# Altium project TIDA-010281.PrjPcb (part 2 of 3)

## Sheet TIDA-010281_PMIC_BUCK.SchDoc
size 558 x 431 mm; Date: Not shown in title block; ApprovedBy: Not shown in title block; CheckedBy: Not shown in title block; Author: Not shown in title block; CompanyName: Not shown in title block; Engineer: Not shown in title block; Organization: Not shown in title block; Address1: Not shown in title block; Address2: Not shown in title block; Address3: Not shown in title block; Address4: Not shown in title block; DocumentNumber: 5; Revision: Use project parameter SCH_Rev; SheetNumber: 5; SheetTotal: 10; PageSetup: Record=PageOptions¦CenterHorizontal=True¦CenterVertical=True¦PrintScale=1.00¦XCorrection=1.00¦YCorrection=1.00¦PrintKind=0¦BorderSize=5000000¦LeftOffset=0¦BottomOffset=0¦Orientation=2¦PaperLength=1000¦PaperWidth=1000¦Scale=100¦PaperSource=15¦PrintQuality=600¦MediaType=1¦DitherType=10¦PaperKind=Letter¦PrintScaleMode=1
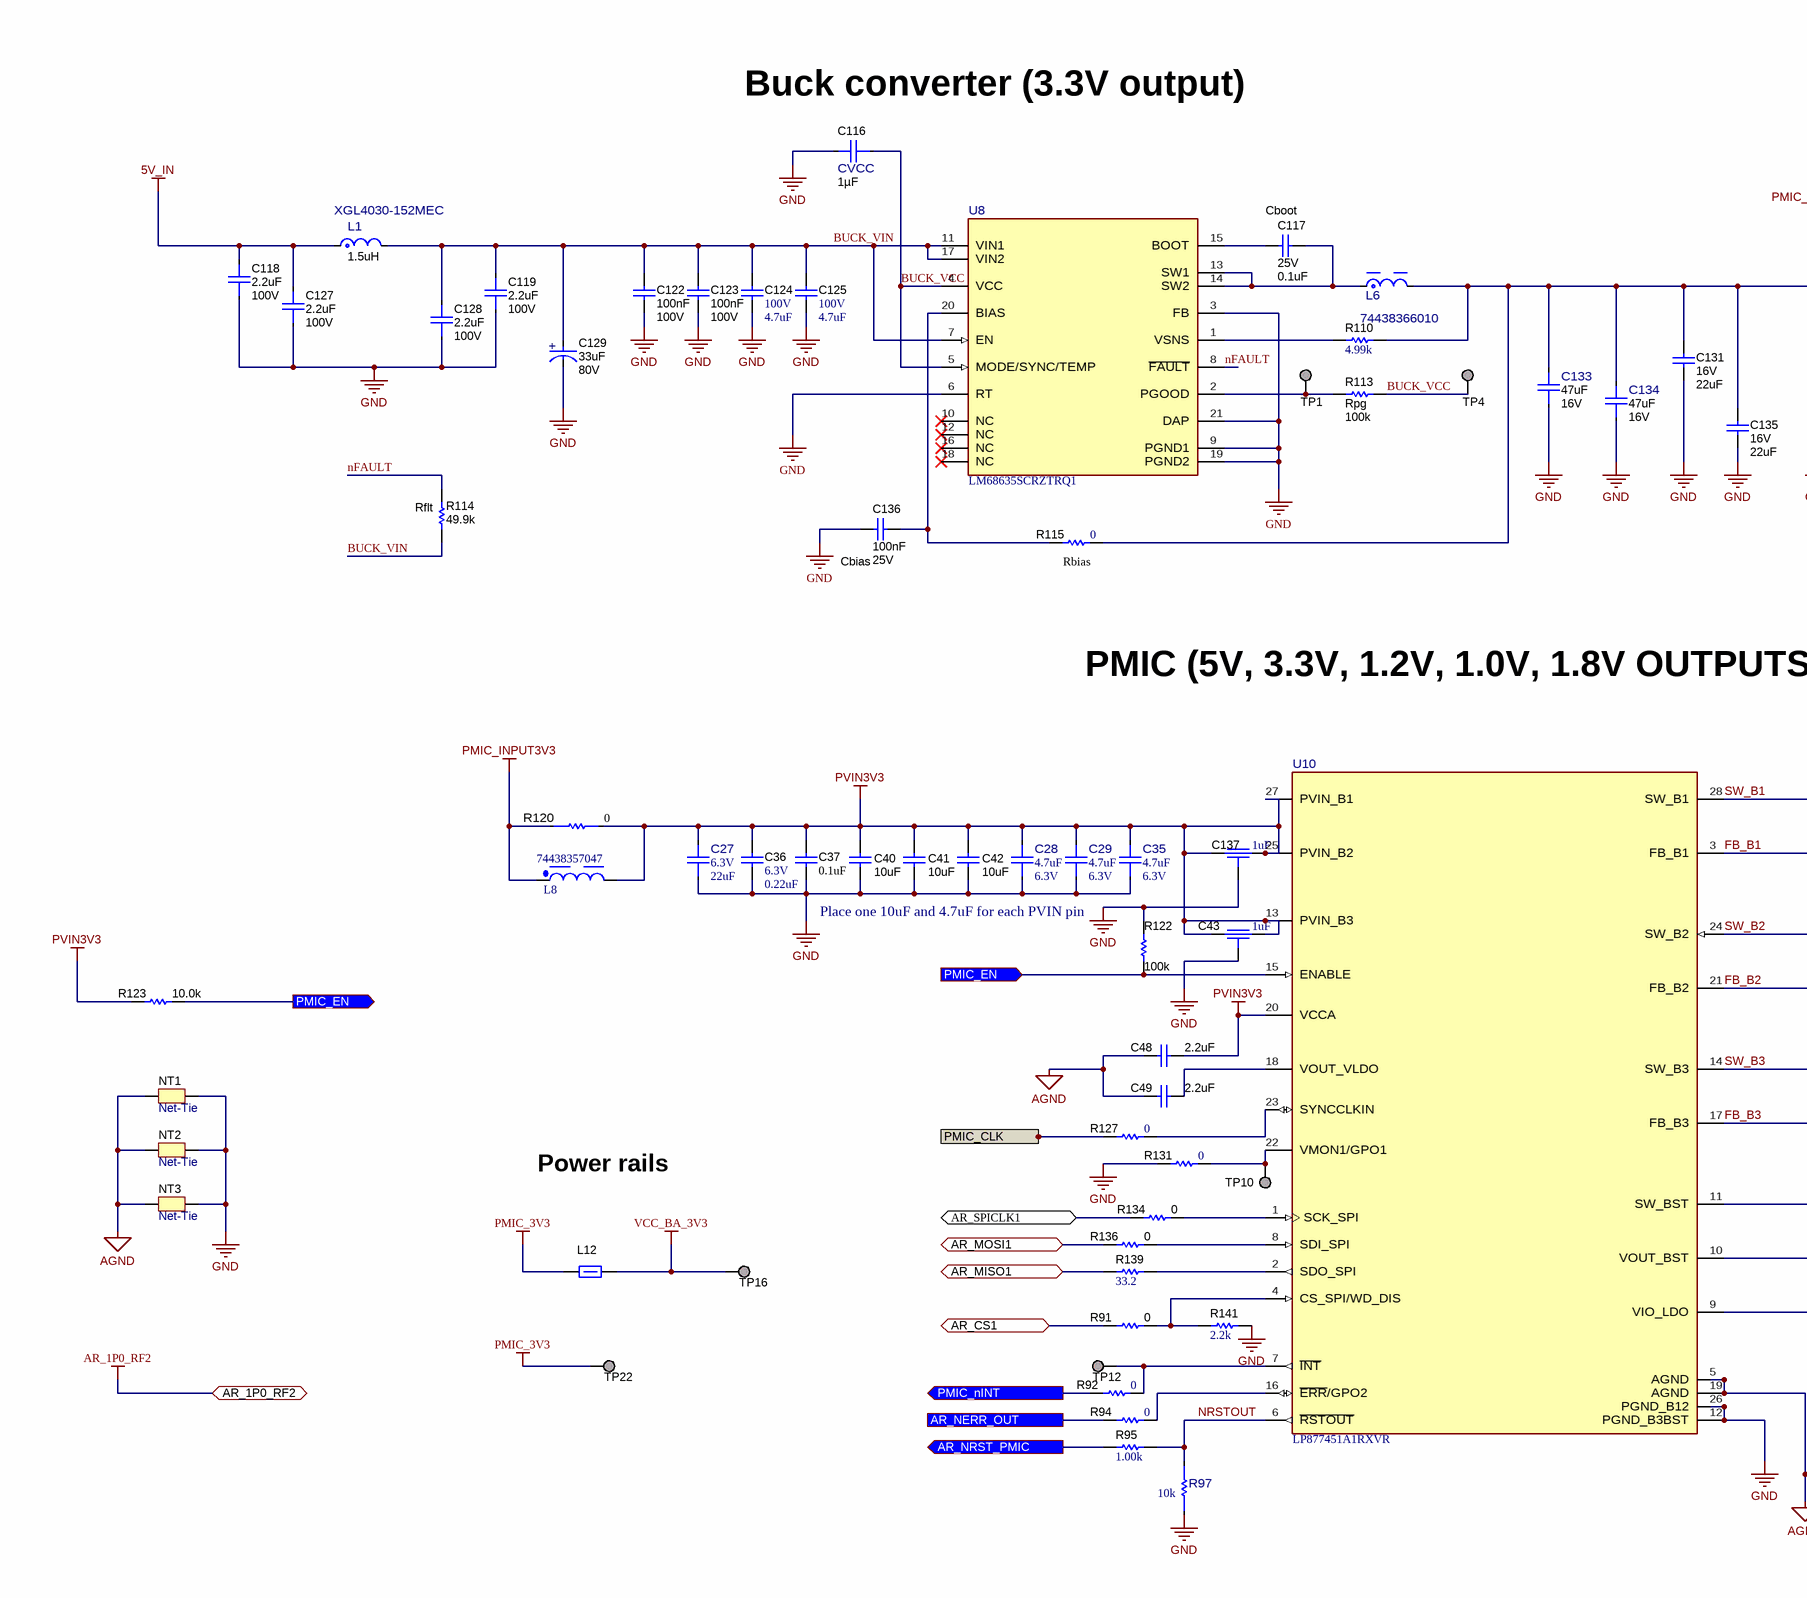
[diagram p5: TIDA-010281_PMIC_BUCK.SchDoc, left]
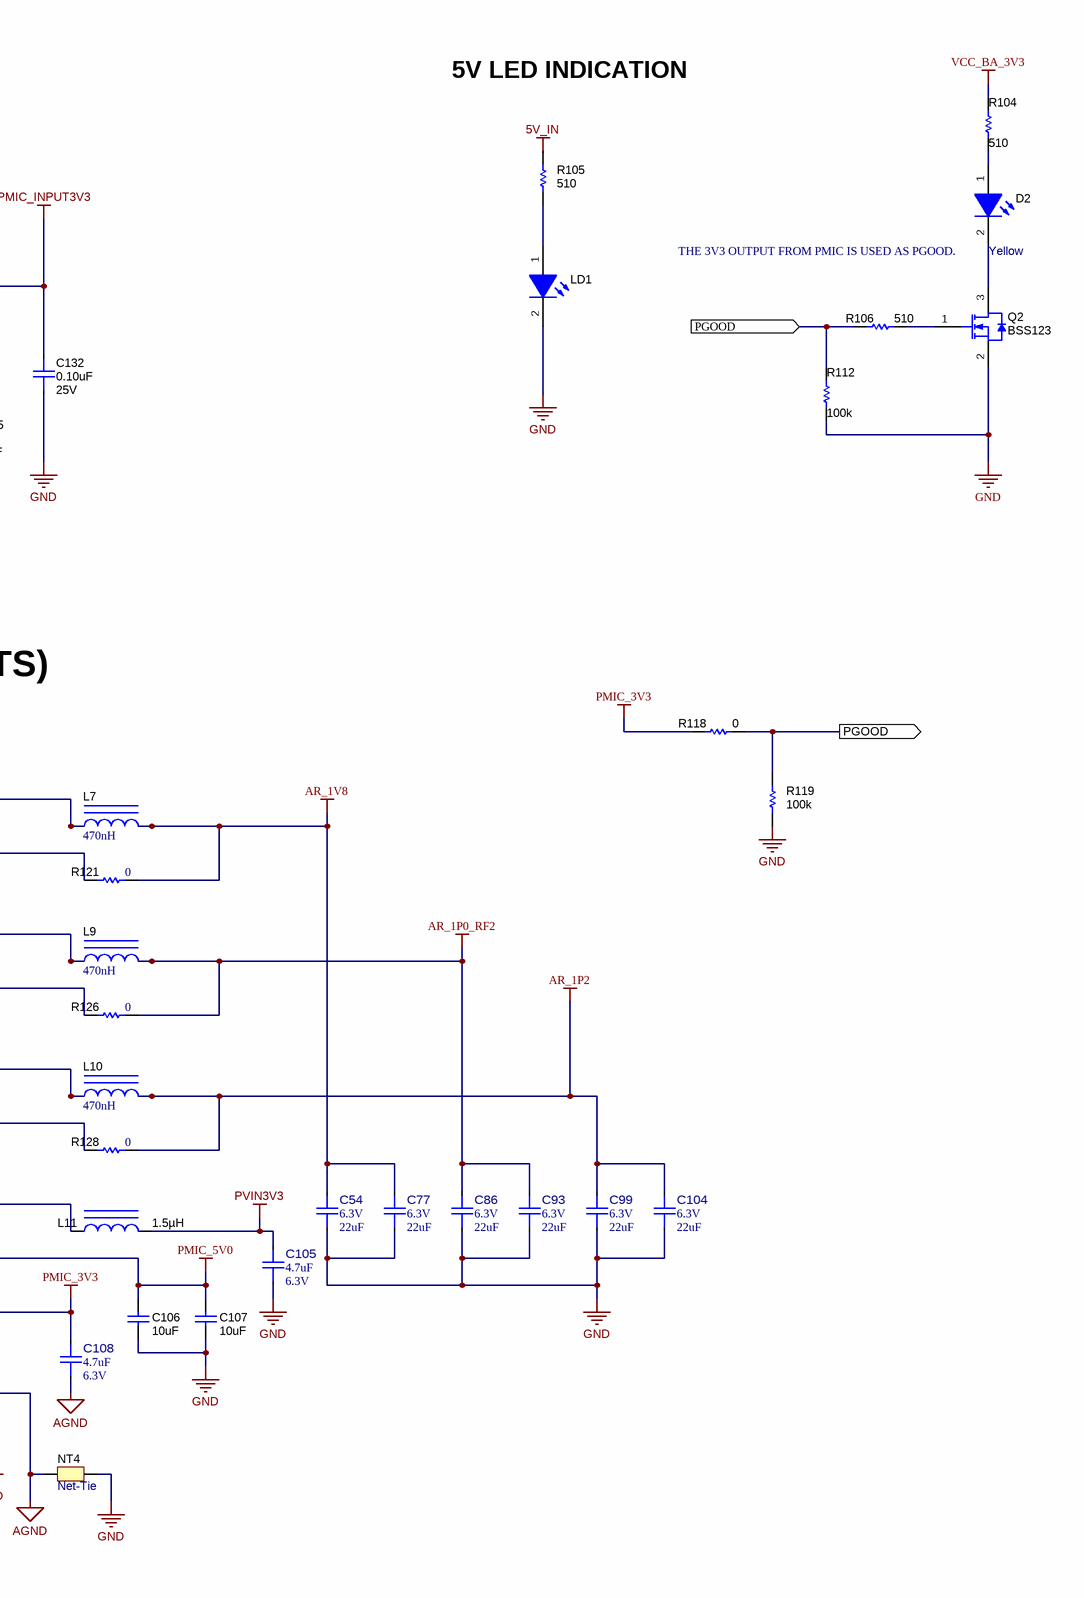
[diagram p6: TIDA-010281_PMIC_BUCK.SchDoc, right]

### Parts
C27  VDC_V: 6.3V  ValueDisplayed: 22uF  [FP-GRM187R60J226ME15D_0603-MFG]  (hidden comment: GRM187R60J226ME15D)
C28  ValueDisplayed: 4.7uF  VDC_V: 6.3V  [FP-885012106005_0603-MFG]  (hidden comment: 885012106005)
C29  ValueDisplayed: 4.7uF  VDC_V: 6.3V  [FP-885012106005_0603-MFG]  (hidden comment: 885012106005)
C35  ValueDisplayed: 4.7uF  VDC_V: 6.3V  [FP-885012106005_0603-MFG]  (hidden comment: 885012106005)
C36  VDC_V: 6.3V  ValueDisplayed: 0.22uF  [0402]  (hidden comment: GRM155R60J224KE01D)
C37  ValueDisplayed: 0.1uF  [0402L]  (hidden comment: GCM155R71C104KA55D)
C40  ValueDisplayed: 10uF  [0805L]  (hidden comment: GCM21BR71A106KE22L)
C41  ValueDisplayed: 10uF  [0805L]  (hidden comment: GCM21BR71A106KE22L)
C42  ValueDisplayed: 10uF  [0805L]  (hidden comment: GCM21BR71A106KE22L)
C43  ValueDisplayed: 1uF  [FP-NFM18HC105C1C3D_0603-MFG]  (hidden comment: NFM18HC105C1C3D)
C48  ValueDisplayed: 2.2uF  [0603L]  (hidden comment: GCM188R70J225KE22D)
C49  ValueDisplayed: 2.2uF  [0603L]  (hidden comment: GCM188R70J225KE22D)
C54  VDC_V: 6.3V  ValueDisplayed: 22uF  [FP-GRM187R60J226ME15D_0603-MFG]  (hidden comment: GRM187R60J226ME15D)
C77  VDC_V: 6.3V  ValueDisplayed: 22uF  [FP-GRM187R60J226ME15D_0603-MFG]  (hidden comment: GRM187R60J226ME15D)
C86  VDC_V: 6.3V  ValueDisplayed: 22uF  [FP-GRM187R60J226ME15D_0603-MFG]  (hidden comment: GRM187R60J226ME15D)
C93  VDC_V: 6.3V  ValueDisplayed: 22uF  [FP-GRM187R60J226ME15D_0603-MFG]  (hidden comment: GRM187R60J226ME15D)
C99  VDC_V: 6.3V  ValueDisplayed: 22uF  [FP-GRM187R60J226ME15D_0603-MFG]  (hidden comment: GRM187R60J226ME15D)
C104  VDC_V: 6.3V  ValueDisplayed: 22uF  [FP-GRM187R60J226ME15D_0603-MFG]  (hidden comment: GRM187R60J226ME15D)
C105  ValueDisplayed: 4.7uF  VDC_V: 6.3V  [FP-885012106005_0603-MFG]  (hidden comment: 885012106005)
C106  ValueDisplayed: 10uF  [0805L]  (hidden comment: GCM21BR71A106KE22L)
C107  ValueDisplayed: 10uF  [0805L]  (hidden comment: GCM21BR71A106KE22L)
C108  ValueDisplayed: 4.7uF  VDC_V: 6.3V  [FP-885012106005_0603-MFG]  (hidden comment: 885012106005)
C116  CVCC  Cap_F: 1µF  [FP-CGA3E1X7R1C105M080AC_0603-IPC_C]
C117  Cboot  VDC_V: 25V  ValueDisplayed: 0.1uF  [0402L]
C118  ValueDisplayed: 2.2uF  VDC_V: 100V  [FP-GRM21BD72A225ME01K_0805-IPC_C]  (hidden comment: GRM21BD72A225ME01K)
C119  ValueDisplayed: 2.2uF  VDC_V: 100V  [FP-GRM21BD72A225ME01K_0805-IPC_C]  (hidden comment: GRM21BD72A225ME01K)
C122  Cap_F: 100nF  VDC_V: 100V  [0603L]  (hidden comment: HMK107B7104KAHT)
C123  Cap_F: 100nF  VDC_V: 100V  [0603L]  (hidden comment: HMK107B7104KAHT)
C124  VDC_V: 100V  ValueDisplayed: 4.7uF  [1210_220]  (hidden comment: CGA6M3X7S2A475K200AB)
C125  VDC_V: 100V  ValueDisplayed: 4.7uF  [1210_220]  (hidden comment: CGA6M3X7S2A475K200AB)
C127  ValueDisplayed: 2.2uF  VDC_V: 100V  [FP-GRM21BD72A225ME01K_0805-IPC_C]  (hidden comment: GRM21BD72A225ME01K)
C128  ValueDisplayed: 2.2uF  VDC_V: 100V  [FP-GRM21BD72A225ME01K_0805-IPC_C]  (hidden comment: GRM21BD72A225ME01K)
C129  ValueDisplayed: 33uF  VDC_V: 80V  [FP-A767KS336M1KLAE045_RADIAL-MFG]  (hidden comment: A767KS336M1KLAE045)
C131  VDC_V: 16V  ValueDisplayed: 22uF  [1210_280]  (hidden comment: CGA6P1X7R1C226M250AC)
C132  ValueDisplayed: 0.10uF  VDC_V: 25V  [FP-GRM155R71E104KE14J_0402-IPC_C]  (hidden comment: Cohf)
C133  ValueDisplayed: 47uF  VDC_V: 16V  [FP-GRM32EC81C476KE15K_1210-MFG]  (hidden comment: GRM32EC81C476KE15K)
C134  ValueDisplayed: 47uF  VDC_V: 16V  [FP-GRM32EC81C476KE15K_1210-MFG]  (hidden comment: GRM32EC81C476KE15K)
C135  VDC_V: 16V  ValueDisplayed: 22uF  [1210_280]  (hidden comment: CGA6P1X7R1C226M250AC)
C136  Cbias  Cap_F: 100nF  VDC_V: 25V  [0603L]
C137  ValueDisplayed: 1uF  [FP-NFM18HC105C1C3D_0603-MFG]  (hidden comment: NFM18HC105C1C3D)
D2  value Yellow  [TLMx1000_Yellow]  (hidden comment: TLMY1000-GS08)
L1  XGL4030-152MEC  value 1.5uH  [FP-XGL4030-152MEC_SMT2_4MM0_4MM0-MFG]
L6  74438366010  [FP-74438366010_SMT_IND_5MM4_5MM4-MFG]
L7  ValueDisplayed: 470nH  [TFM201610ALMA]  (hidden comment: TFM201610ALMAR47MTAA)
L8  74438357047  [WE-MAPI_4030]
L9  ValueDisplayed: 470nH  [TFM201610ALMA]  (hidden comment: TFM201610ALMAR47MTAA)
L10  ValueDisplayed: 470nH  [TFM201610ALMA]  (hidden comment: TFM201610ALMAR47MTAA)
L11  ValueDisplayed: 1.5µH  [TFM201610ALMA]  (hidden comment: TFM201610ALMA1R5MTAA)
L12  BLM15PD300SZ1D  [0402L]  (value not drawn)
LD1  APHHS1005CGCK  [APHHS1005_Green]  (value not drawn)
NT1  Net-Tie  [Net-Tie_50milWide_30milLong]  (net tie, no BOM)
NT2  Net-Tie  [Net-Tie_50milWide_30milLong]  (net tie, no BOM)
NT3  Net-Tie  [Net-Tie_50milWide_30milLong]  (net tie, no BOM)
NT4  Net-Tie  [Net-Tie_50milWide_30milLong]  (net tie, no BOM)
Q2  BSS123  [SOT-23]
R91  ValueDisplayed: 0  [0402L]  (hidden comment: ERJ-2GE0R00X)
R92  ValueDisplayed: 0  [0402L]  (hidden comment: ERJ-2GE0R00X)
R94  ValueDisplayed: 0  [0402L]  (hidden comment: ERJ-2GE0R00X)
R95  ValueDisplayed: 1.00k  [0402]  (hidden comment: CRCW04021K00FKED)
R97  value 10k  [FP-RC0402FR-0710KL_0402-MFG]  (hidden comment: RC0402FR-0710KL)
R104  ValueDisplayed: 510  [0402L]  (hidden comment: ERJ-2GEJ511X)
R105  value 510  [0201L]  (hidden comment: RC0201JR-07510RL)
R106  ValueDisplayed: 510  [0402L]  (hidden comment: ERJ-2GEJ511X)
R110  ValueDisplayed: 4.99k  [0402]  (hidden comment: CRCW04024K99FKED)
R112  ValueDisplayed: 100k  [0402L]  (hidden comment: CRCW0402100KFKED)
R113  Rpg  ValueDisplayed: 100k  [0603L]
R114  Rflt  ValueDisplayed: 49.9k  [0603L]
R115  ValueDisplayed: 0  [0402L]  (hidden comment: ERJ-2GE0R00X)
R118  Res_ohm: 0  [FP-RC0201JR-070RL_0201 (0603 Metric)-MFG]  (hidden comment: RC0201JR-070RL)
R119  value 100k  [0201L]  (hidden comment: CRCW0201100KFKED)
R120  Res_ohm: 0  [FP-HCJ0603ZT0R00_0603-MFG]  (hidden comment: HCJ0603ZT0R00)
R121  ValueDisplayed: 0  [0402L]  (hidden comment: ERJ-2GE0R00X)
R122  ValueDisplayed: 100k  [0402L]  (hidden comment: CRCW0402100KFKED)
R123  ValueDisplayed: 10.0k  [0402L]  (hidden comment: CRCW040210K0FKED)
R126  ValueDisplayed: 0  [0402L]  (hidden comment: ERJ-2GE0R00X)
R127  ValueDisplayed: 0  [0402L]  (hidden comment: ERJ-2GE0R00X)
R128  ValueDisplayed: 0  [0402L]  (hidden comment: ERJ-2GE0R00X)
R131  ValueDisplayed: 0  [0402L]  (hidden comment: ERJ-2GE0R00X)
R134  ValueDisplayed: 0  [0402L]  (hidden comment: ERJ-2GE0R00X)
R136  ValueDisplayed: 0  [0402L]  (hidden comment: ERJ-2GE0R00X)
R139  ValueDisplayed: 33.2  [0402]  (hidden comment: CRCW040233R2FKED)
R141  ValueDisplayed: 2.2k  [0402]  (hidden comment: CRCW04022K20JNED)
TP1  TESTPOINT  [TP_25MIL-SMT]  (value not drawn)  (no BOM)
TP4  TESTPOINT  [TP_25MIL-SMT]  (value not drawn)  (no BOM)
TP10  TESTPOINT  [TP_25MIL-SMT]  (value not drawn)  (no BOM)
TP12  TESTPOINT  [TP_VIA_060RND040]  (value not drawn)  (no BOM)
TP16  TESTPOINT  [TP_25MIL-SMT]  (value not drawn)  (no BOM)
TP22  TESTPOINT  [TP_25MIL-SMT]  (value not drawn)  (no BOM)
U8  LM68635SCRZTRQ1  [RZT0020A-MFG]
U10  PartNumber: LP877451A1RXVR  [RXV0028A-MFG]  (hidden comment: LP877451A1RXVRQ1)

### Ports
AR_1P0_RF2 (bidir), AR_CS1 (bidir), AR_MISO1 (bidir), AR_MOSI1 (bidir), AR_NERR_OUT, AR_NRST_PMIC (out), AR_SPICLK1 (bidir), PGOOD (in), PGOOD (out), PMIC_CLK (in), PMIC_EN (in), PMIC_EN (out), PMIC_nINT (out)

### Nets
5V_IN: C118.2 C127.2 L1.1 R105.1
AGND: C48.1 C49.1 C108.1 NT1.1 NT2.1 NT3.1 NT4.2 U10.5(AGND) U10.19(AGND)
AR_1P0_RF2: C86.2 C93.2 L9.2 R126.2 ; port AR_1P0_RF2
AR_1P2: C99.2 C104.2 L10.2 R128.2
AR_1V8: C54.2 C77.2 L7.2 R121.2
GND: C27.1 C28.1 C29.1 C35.1 C36.2 C37.2 C40.2 C41.2 C42.2 C43.2 C54.1 C77.1 C86.1 C93.1 C99.1 C104.1 C105.1 C106.2 C107.2 C116.2 C118.1 C119.1 C122.2 C123.2 C124.2 C125.2 C127.1 C128.1 C129.1(CATHODE) C131.2 C132.1 C133.1 C134.1 C135.2 C136.2 C137.2 LD1.2(K) NT1.2 NT2.2 NT3.2 NT4.1 Q2.2(S) R97.1 R112.1 R119.1 R122.2 R131.1 R141.2 U8.3(FB) U8.6(RT) U8.9(PGND1) U8.19(PGND2) U8.21(DAP) U10.12(PGND_B3BST) U10.26(PGND_B12)
PMIC_3V3: C108.2 L12.1 R118.2 TP22.1 U10.9(VIO_LDO)
PMIC_5V0: C106.1 C107.1 U10.10(VOUT_BST)
PMIC_INPUT3V3: C131.1 C132.2 C133.2 C134.2 C135.1 L6.2 L8.1 R110.2 R115.2 R120.1
PVIN3V3: C27.2 C28.2 C29.2 C35.2 C36.1 C37.1 C40.1 C41.1 C42.1 C43.1 C43.3 C48.2 C105.2 C137.1 C137.3 L8.2 L11.2 R120.2 R123.2 U10.13(PVIN_B3) U10.20(VCCA) U10.25(PVIN_B2) U10.27(PVIN_B1)
VCC_BA_3V3: L12.2 R104.2 TP16.1
AR_CS1: R91.1 ; port AR_CS1
AR_MISO1: R139.1 ; port AR_MISO1
AR_MOSI1: R136.2 ; port AR_MOSI1
AR_NERR_OUT: R94.1 ; port AR_NERR_OUT
AR_NRST_PMIC: R95.1 ; port AR_NRST_PMIC
AR_SPICLK1: R134.2 ; port AR_SPICLK1
BUCK_VCC: C116.1 R113.1 TP4.1 U8.4(VCC) U8.5(MODE/SYNC/TEMP)
BUCK_VIN: C119.2 C122.1 C123.1 C124.1 C125.1 C128.2 C129.2(ANODE) L1.2 R114.1 U8.7(EN) U8.11(VIN1) U8.17(VIN2)
FB_B1: R121.1 U10.3(FB_B1)
FB_B2: R126.1 U10.21(FB_B2)
FB_B3: R128.1 U10.17(FB_B3)
nFAULT: R114.2 U8.8(~{FAULT})
NRSTOUT: R95.2 R97.2 U10.6(~{RSTOUT})
PGOOD: R106.1 R112.2 R118.1 R119.2 ; port PGOOD
PMIC_CLK: R127.1 ; port PMIC_CLK
PMIC_EN: R122.1 R123.1 U10.15(ENABLE) ; port PMIC_EN
PMIC_nINT: R92.1 ; port PMIC_nINT
SW_B1: L7.1 U10.28(SW_B1)
SW_B2: L9.1 U10.24(SW_B2)
SW_B3: L10.1 U10.14(SW_B3)
NetC49_2: C49.2 U10.18(VOUT_VLDO)
NetC117_1: C117.1 L6.1 U8.13(SW1) U8.14(SW2)
NetC117_2: C117.2 U8.15(BOOT)
NetC136_1: C136.1 R115.1 U8.20(BIAS)
NetD2_1: D2.1(A) R104.1
NetD2_2: D2.2(K) Q2.3(D)
NetL11_1: L11.1 U10.11(SW_BST)
NetLD1_1: LD1.1(A) R105.2
NetQ2_1: Q2.1(G) R106.2
NetR91_2: R91.2 R141.1 U10.4(CS_SPI/WD_DIS)
NetR92_2: R92.2 TP12.1 U10.7(~{INT})
NetR94_2: R94.2 U10.16(~{ERR}/GPO2)
NetR110_1: R110.1 U8.1(VSNS)
NetR113_2: R113.2 TP1.1 U8.2(PGOOD)
NetR127_2: R127.2 U10.23(SYNCCLKIN)
NetR131_2: R131.2 TP10.1 U10.22(VMON1/GPO1)
NetR134_1: R134.1 U10.1(SCK_SPI)
NetR136_1: R136.1 U10.8(SDI_SPI)
NetR139_2: R139.2 U10.2(SDO_SPI)

Not connected (* = marked no-connect by the designer): U8 10(NC)* 12(NC)* 16(NC)* 18(NC)*

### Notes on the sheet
- 5V LED INDICATION
- (near C116) Buck converter (3.3V output)
- THE 3V3 OUTPUT FROM PMIC IS USED AS PGOOD.
- (near R115) Rbias
- PMIC (5V, 3.3V, 1.2V, 1.0V, 1.8V OUTPUTS)
- Place one 10uF and 4.7uF for each PVIN pin
- Power rails

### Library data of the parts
C27 C54 C77 C86 C93 C99 C104 = CMP-0090352-1: 22µF ±20% 6.3V Ceramic Capacitor X5R 0603 (1608 Metric); Manufacturer: Murata; TempCo: 15%; AEC Qualified: No; SizeZ_mm: 0.8mm
C28 C29 C35 C105 C108 = CMP-0049191-1: 4.7 µF ±20% 6.3V Ceramic Capacitor X5R 0603 (1608 Metric); Manufacturer: Wurth Electronics; AEC Qualified: No; Cap_F: 4.7µF; SizeZ_mm: 1mm; TempCo: 15%; Value: 4.7µF
C36 = CMP-0006542-2: CAP, CERM, 0.22 uF, 6.3 V, +/- 10%, X5R, 0402; Manufacturer: MuRata; TaMin_C: -55°C; Polarized: N; SizeAreaWB_mm2: 3; Value1: Unknown; U/M: EA; Value: 0.22uF; TaMax_C: 85°C; SizeZ_mm: 0.6; SizeX_mm: 1; SizeY_mm: 0.5; Cap_F: 220nF; AEC Category: Q200
C37 = CMP-0006351-2: CAP, CERM, 0.1 uF, 16 V, +/- 10%, X7R, 0402; Manufacturer: MuRata; TaMin_C: -55°C; Polarized: N; SizeAreaWB_mm2: 3; Value1: Unknown; U/M: EA; Value: 0.1uF; TaMax_C: 125°C; SizeZ_mm: 0.6; SizeX_mm: 1; SizeY_mm: 0.5; Cap_Case: 0402; Value2: 16V; Cap_F: 100nF; AEC Category: Q200
C40-C42 C106 C107 = CMP-0008017-2: CAP, CERM, 10 uF, 10 V, +/- 10%, X7R, 0805; Manufacturer: MuRata; TaMin_C: -55°C; Polarized: N; SizeAreaWB_mm2: 6.75; Value1: Unknown; U/M: EA; Value: 10uF; TaMax_C: 125°C; SizeZ_mm: 1.45; SizeX_mm: 2; SizeY_mm: 1.25; Cap_Case: 0805; Value2: 10V; SizeArea_mm2: 2.5; Cap_F: 10µF; AEC Category: Q200
C43 C137 = CMP-0088247-2: 3 Terminals Low ESL Chip Multilayer Ceramic Capacitors for Automotive; Manufacturer: Murata; VDC_V: 16V; SizeZ_mm: 0.7mm; Tolerance_%: 20%; AEC Grade: Grade 1; Cap_F: 1µF; AEC Qualified: Yes
C48 C49 = CMP-0007134-5: CAP, CERM, 2.2 uF, 6.3 V, +/- 10%, X7R, AEC-Q200 Grade 1, 0603; Manufacturer: MuRata; TaMin_C: -55°C; Polarized: N; SizeAreaWB_mm2: 4.68; Value1: Unknown; U/M: EA; Value: 2.2uF; TaMax_C: 125°C; SizeZ_mm: 1; SizeX_mm: 1.6; SizeY_mm: 0.8; Cap_Case: 0603; Value2: 6.3V; SizeArea_mm2: 1.28; AEC Qualified: Y; Cap_F: 2.2µF; AEC Category: Q200
C116 = CMP-0095369-1: Cap Ceramic 1uF 16V X7R 20% Pad SMD 0603 +125°C Automotive T/R; PartNumber: CGA3E1X7R1C105M080AC; Manufacturer: TDK; AEC Qualified: Yes; Tolerance_%: 0.2%; SizeZ_mm: 1.1mm; Value: 1µF; TempCo: 0.15; AEC Grade: Grade 1
C117 = CMP-0006295-2: CAP, CERM, 0.1 uF, 25 V, +/- 20%, X7R, 0402; Manufacturer: TDK; PartNumber: C1005X7R1E104M050BB; TaMin_C: -55°C; Polarized: N; SizeAreaWB_mm2: 3; Value1: Unknown; U/M: EA; Value: 0.1uF; TaMax_C: 125°C; SizeZ_mm: 0.6; SizeX_mm: 1; SizeY_mm: 0.5; Cap_Case: 0402; CompType: Capacitor; Cap_F: 100nF; AEC Category: Q200
C118 C119 C127 C128 = CMP-0096278-1: Chip Multilayer Ceramic Capacitor for General Purpose 2.2uF ±20% 100V X7T SMD 0805; Manufacturer: Murata; AEC Qualified: No; Cap_F: 2.2µF; Value: 2.2µF; SizeZ_mm: 1.45mm; TempCo: +22/-33%
C122 C123 = CMP-0081011-1: CAP, CERM, 0.1 µF, 100 V,+/- 10%, X7R, AEC-Q200 Grade 1, 0603; Manufacturer: Taiyo Yuden; SizeAreaWB_mm2: 4.68; SizeArea_mm2: 1.28; AEC Qualified: Y; AEC Category: Q200; Value: 0.1uF; TaMax_C: 125°C; SizeZ_mm: 1; Polarized: N; TaMin_C: -55°C; SizeY_mm: 0.8; U/M: EA; CompType: Capacitor; SizeX_mm: 1.6; Cap_Case: 0603; ValueDisplayed: 0.1µF
C124 C125 = CMP-0009150-2: CAP, CERM, 4.7 uF, 100 V, +/- 10%, X7S, AEC-Q200 Grade 1, 1210; Manufacturer: TDK; TaMin_C: -55°C; ESR_ohm: 4.236m; Polarized: N; SizeAreaWB_mm2: 14.7; Value1: 0.004236 ohm; U/M: EA; Value: 4.7uF; TaMax_C: 125°C; SizeZ_mm: 2.2; SizeX_mm: 3.2; SizeY_mm: 2.5; SizeArea_mm2: 8; AEC Qualified: Y; Cap_F: 4.7µF; IRMS_A: 3.57337A; AEC Grade: 1; AEC Category: Q200
C129 = CMP-0096303-1: 33 µF 80 V Aluminum - Polymer Capacitors Radial, Can - SMD 45mOhm 2000 Hrs @ 105°C; Manufacturer: KEMET; Life: 2000Hours; AEC Qualified: No; Value: 33µF; Tolerance_%: 20%; SizeZ_mm: 12.5mm; Esr: 0.045; IRMS_A: 2.1A; Leakage Current: 528uA
C131 C135 = CMP-0009154-2: CAP, CERM, 22 uF, 16 V, +/- 20%, X7R, AEC-Q200 Grade 1, 1210; Manufacturer: TDK; TaMin_C: -55°C; ESR_ohm: 2.582m; Polarized: N; SizeAreaWB_mm2: 14.7; Value1: 0.002582 ohm; U/M: EA; Value: 22uF; TaMax_C: 125°C; SizeZ_mm: 2.8; SizeX_mm: 3.2; SizeY_mm: 2.5; SizeArea_mm2: 8; CompType: Capacitor; AEC Qualified: Y; Cap_F: 22µF; IRMS_A: 4.57562A; AEC Grade: 1; AEC Category: Q200
C132 = CMP-0095279-1: Chip Multilayer Ceramic Capacitors for General Purpose, 0402, 0.10uF, X7R, 15%, 10%, 25V; Manufacturer: Murata; Part Number: GRM155R71E104KE14J; Value: 100nF; SizeZ_mm: 0.55mm; AEC Qualified: No
C133 C134 = CMP-0095373-1: Chip Multilayer Ceramic Capacitors for General Purpose, 1210, 47uF, X6S, 22%, 10%, 16V; Manufacturer: Murata; Cap_F: 47µF; AEC Qualified: No; Value: 47µF; SizeZ_mm: 2.7mm
C136 = CMP-0006753-4: CAP, CERM, 0.1 uF, 25 V, +/- 10%, X7R, 0603; Manufacturer: AVX; PartNumber: 06033C104KAT2A; TaMin_C: -55°C; ESR_ohm: 0.05; Polarized: N; SizeAreaWB_mm2: 4.68; Value1: 0.05 ohm; U/M: EA; Value: 0.1uF; TaMax_C: 125°C; SizeZ_mm: 1; SizeX_mm: 1.6; SizeY_mm: 0.8; Cap_Case: 0603; SizeArea_mm2: 1.28; CompType: Capacitor; AEC Category: Q200
D2 = CMP-0078196-2: LED, Yellow, SMD; Manufacturer: Vishay-Semiconductor; Tjmax_C: 120°C; SizeAreaWB_mm2: 4.68; Vr_V: 6V; Power_TotalModule: 40mW; Angle: 160; SizeArea_mm2: 1.28; Ir_A: 10µA; SizeZ_mm: 0.65; Io_A: 2mA; Vf_V: 1.8V; SizeY_mm: 0.8; Value1: .04W; SizeX_mm: 1.6; Type: AlInGaP
L1 = CMP-0092596-1: Shielded Power Inductors 1.5 µH 10.2A 10.5mOhm Max Nonstandard; Manufacturer: Coilcraft; Isat: 3.8A; Tolerance_%: 20%; AEC Grade: Grade 1; Self Resonant Frequency: 50MHz; TaMin_C: -40°C; Test Frequency: 1MHz; Material: Composite; DCR_ohm: 0.0105; TaMax_C: +125°C; AEC Qualified: Yes; SizeZ_mm: 3.1mm; Ind_H: 1.5µH; Shrouded: true
L6 = CMP-0095717-1: 1 µH Shielded - Inductor 7.8 A 13.1mOhm Max Nonstandard; Manufacturer: Wurth Electronics; Value: 1uH; Self Resonant Frequency: 50MHz; TaMax_C: +85°C; Tolerance_%: 20%; Isat: 10A; SizeZ_mm: 2.1mm; Test Frequency: 100kHz; Irms: 7.8A; AEC Qualified: No; DCR_ohm: 13.1m; Shrouded: true; Ind_H: 1µH; TaMin_C: -40°C; Material: Magnetic Iron
L7 L9 L10 = CMP-0081095-1: Inductor, Shielded, Metal Composite, 470 nH, 3.9 A, 0.039 ohm, AEC-Q200 Grade 0, SMD; Manufacturer: TDK; Isat: 4.5A @ 30% inductance drop; Irms: 3.9A @ 40C rise; SizeAreaWB_mm2: 7.8; DCR_ohm: 0.039; Value: 470nH; Imax_A: 3.9A; SizeZ_mm: 1; SizeX_mm: 2; SizeY_mm: 1.6; SizeArea_mm2: 3.2; AEC Qualified: Y; AEC Grade: 0; AEC Category: Q200
L8 = CMP-0099162-1: WE-MAPI SMT Power Inductor, size 4030, 4.7uH, 3.9A, 44mOhm; Manufacturer: Wurth Elektronik; Case/Size Code: 4030; DC Resistance: 39.9mOhm; Saturation Current: 6.4A; Self Resonant Frequency: 24MHz
L11 = CMP-0081093-1: Inductor, Shielded, Metal Composite, 1.5 µH, 2.3 A, 0.11 ohm, AEC-Q200 Grade 0, SMD; Manufacturer: TDK; Isat: 2.8A @ 30% inductance drop; Irms: 2.3A @ 40C rise; SizeAreaWB_mm2: 7.8; DCR_ohm: 0.11; Value: 1.5uH; Imax_A: 2.3A; SizeZ_mm: 1; SizeX_mm: 2; SizeY_mm: 1.6; SizeArea_mm2: 3.2; AEC Qualified: Y; AEC Grade: 0; AEC Category: Q200
L12 = CMP-0078934-1: Inductor, Ferrite Bead, Ferrite, 2.2 A, 0.035 ohm, AEC-Q200 Grade 1, SMD; Manufacturer: MuRata; AEC Category: Q200; AEC Grade: 1; AEC Qualified: Y; DCR_ohm: 0.035; Imax_A: 2.2A; SizeArea_mm2: 0.5; SizeAreaWB_mm2: 3; SizeZ_mm: 0.6
LD1 = CMP-0067682-2: LED, Green, SMD; Manufacturer: Kingbright; Angle: 120.0; Power_TotalModule: 75mW; SizeZ_mm: 0.6; Vf_V: 2.1V; Vr_V: 5V; Io_A: 20mA; Ir_A: 10µA; SizeArea_mm2: 0.5; SizeAreaWB_mm2: 3.0; SizeX_mm: 1.0; Tjmax_C: 85°C; Value1: 0.075W
NT1-NT3 = CMP-0078142-3: Single point connection between nets.
NT4 = CMP-0078142-4: Single point connection between nets.
Q2 = CMP-0000947-2: MOSFET, N-CH, 100 V, 0.17 A, SOT-23; Alternate Manufacturer: None; Manufacturer: Fairchild Semiconductor; SizeZ_mm: 1.1; ChType: N; Value2: 1.8 nC; Value1: 1; VdsMax_V: 100V; SizeX_mm: 2.5; SizeY_mm: 3; Vgs_V: 20V; Value: 100V; Rdson45_ohm: 10; SizeArea_mm2: 7.5; AEC Category: Q101; IdsMax_A: 1.7dA; SizeAreaWB_mm2: 14; U/M: EA; QgTyp_nC: 1.8
R91 R134 R136 = CMP-0026992-3: RES, 0, 5%, 0.1 W, AEC-Q200 Grade 0, 0402; Manufacturer: Panasonic; Power_W: 100mW; TempCo: 600 ppm/C; Value_Code: 0000; Value: 0; EIA_Code: E24; SizeX_mm: 1; SizeY_mm: 0.5; SizeZ_mm: 0.6; Value2: 0.1W; AEC Qualified: Y; VDC_V: 50V; AEC Category: Q200; SizeAreaWB_mm2: 3
R92 R94 R115 R121 R126-R128 R131 = CMP-0026992-3: RES, 0, 5%, 0.1 W, AEC-Q200 Grade 0, 0402; Manufacturer: Panasonic; Power_W: 100mW; TempCo: 600 ppm/C; Value_Code: 0000; Value: 0; EIA_Code: E24; SizeX_mm: 1; SizeY_mm: 0.5; SizeZ_mm: 0.6; Value2: 0.1W; CompType: Resistor; AEC Qualified: Y; VDC_V: 50V; AEC Category: Q200; SizeAreaWB_mm2: 3; INSTALLATION: DNP
R95 = CMP-0026071-3: RES, 1.00 k, 1%, 0.063 W, AEC-Q200 Grade 0, 0402; Manufacturer: Vishay-Dale; Power_W: 63mW; TempCo: 100 ppm/C; Value_Code: 1k00; Value: 1.00k; EIA_Code: E96; Res_ohm: 1k; SizeX_mm: 1; SizeY_mm: 0.5; SizeZ_mm: 0.6; Value2: 0.063W; AEC Qualified: Y; VDC_V: 50V; AEC Category: Q200; AEC Grade: 0
R97 = CMP-0001699-1: 10 kOhms ±1% 0.063W, 1/16W Chip Resistor 0402 (1005 Metric) Moisture Resistant Thick Film; Manufacturer: Yageo; AEC Qualified: No; Power_W: 63mW; SizeZ_mm: 0.4mm; TempCo: 100ppm/°C; VDC_V: 50V
R104 R106 = CMP-0078212-1: RES, 510, 5%, 0.1 W, AEC-Q200 Grade 0, 0402; Manufacturer: Panasonic; Value_Code: 510R; SizeArea_mm2: 0.5; AEC Qualified: Y; AEC Category: Q200; Value: 510; SizeZ_mm: 0.6; EIA_Code: E24; TempCo: 200 ppm/C; AEC Grade: 0; Power_W: 100mW; VDC_V: 50V; Value2: 0.1W; U/M: EA; SizeX_mm: 1
R105 = CMP-0027137-1: RES, 510, 5%, 0.05 W, 0201; Manufacturer: Yageo America; AEC Category: Q200; AEC Qualified: N; EIA_Code: E24; Power_W: 50mW; SizeArea_mm2: 0.18; SizeX_mm: 0.6; SizeY_mm: 0.3; SizeZ_mm: 0.26; TempCo: 200 ppm/C; U/M: EA; Value2: 0.05W; Value_Code: 510R; VDC_V: 25V
R110 = CMP-0026414-2: RES, 4.99 k, 1%, 0.063 W, AEC-Q200 Grade 0, 0402; Manufacturer: Vishay-Dale; Power_W: 63mW; TempCo: 100 ppm/C; Value_Code: 4k99; Value: 4.99k; EIA_Code: E96; SizeX_mm: 1; SizeY_mm: 0.5; SizeZ_mm: 0.6; Value2: 0.063W; AEC Qualified: Y; VDC_V: 50V; AEC Category: Q200; AEC Grade: 0
R112 R122 = CMP-0025950-3: RES, 100 k, 1%, 0.063 W, AEC-Q200 Grade 0, 0402; Manufacturer: Vishay-Dale; Power_W: 63mW; TempCo: 100 ppm/C; Value: 100k; EIA_Code: E96; SizeX_mm: 1; SizeY_mm: 0.5; SizeZ_mm: 0.6; Value2: 0.063W; AEC Qualified: Y; VDC_V: 50V; AEC Category: Q200; AEC Grade: 0
R113 = CMP-0022735-3: RES, 100 k, 1%, 0.1 W, 0603; Manufacturer: Yageo America; PartNumber: RC0603FR-07100KL; Power_W: 100mW; TempCo: 200 ppm/C; U/M: EA; Value: 100k; EIA_Code: E96; SizeX_mm: 1.6; SizeY_mm: 0.8; SizeZ_mm: 1; Value2: 0.1W; SizeArea_mm2: 1.28; CompType: Resistor; VDC_V: 150V; AEC Category: Q200
R114 = CMP-0023142-5: RES, 49.9 k, 1%, 0.1 W, 0603; Manufacturer: Yageo; PartNumber: RC0603FR-0749K9L; Power_W: 100mW; TempCo: 100 ppm/C; Value_Code: 49k9; Value: 49.9k; EIA_Code: E96; SizeX_mm: 1.6; SizeY_mm: 0.8; SizeZ_mm: 1; Value2: 0.1W; SizeArea_mm2: 1.28; CompType: Resistor; AEC Qualified: N; VDC_V: 75V; AEC Category: Q200; SizeAreaWB_mm2: 4.68
R118 = CMP-0086442-2: RES SMD 0 OHM JUMPER 1/20W 0201; Manufacturer: Yageo; AEC Qualified: No; Power_W: 50mW; SizeZ_mm: 0.26mm; TempCo: 200ppm/°C; Tolerance_%: 5%; VDC_V: 25V
R119 = CMP-0027261-3: RES, 100 k, 1%, 0.05 W, 0201; Manufacturer: Vishay-Dale; AEC Category: Q200; AEC Qualified: N; EIA_Code: E96; Power_W: 50mW; SizeArea_mm2: 0.18; SizeX_mm: 0.6; SizeY_mm: 0.3; SizeZ_mm: 0.26; TempCo: 100 ppm/C; Value2: 0.05W; VDC_V: 30V
R120 = CMP-0091690-1: RES 0 OHM JUMPER 1/4W 0603; Manufacturer: Stackpole Electronics; Power_W: 250mW; AEC Grade: Grade 0; AEC Qualified: Yes; SizeZ_mm: 0.7mm; Value: 0
R123 = CMP-0025958-3: RES, 10.0 k, 1%, 0.063 W, AEC-Q200 Grade 0, 0402; Manufacturer: Vishay-Dale; Power_W: 63mW; TempCo: 100 ppm/C; Value_Code: 10k0; Value: 10.0k; EIA_Code: E96; Res_ohm: 10k; SizeX_mm: 1; SizeY_mm: 0.5; SizeZ_mm: 0.6; Value2: 0.063W; AEC Qualified: Y; VDC_V: 50V; AEC Category: Q200; AEC Grade: 0
R139 = CMP-0026299-2: RES, 33.2, 1%, 0.063 W, AEC-Q200 Grade 0, 0402; Manufacturer: Vishay-Dale; Power_W: 63mW; TempCo: 100 ppm/C; Value_Code: 33R2; Value: 33.2; EIA_Code: E96; SizeX_mm: 1; SizeY_mm: 0.5; SizeZ_mm: 0.6; Value2: 0.063W; AEC Qualified: Y; VDC_V: 50V; AEC Category: Q200; AEC Grade: 0
R141 = CMP-0026890-5: RES, 2.2 k, 5%, 0.063 W, AEC-Q200 Grade 0, 0402; Manufacturer: Vishay-Dale; Power_W: 63mW; TempCo: 200 ppm/C; Value_Code: 2k20; Value: 2.2k; EIA_Code: E24; SizeX_mm: 1; SizeY_mm: 0.5; SizeZ_mm: 0.6; Value2: 0.063W; AEC Qualified: Y; VDC_V: 50V; AEC Category: Q200; AEC Grade: 0
TP1 TP4 TP10 TP12 TP16 TP22 = CMP-0078143-3: TEST POINT.  No entry in BOM.
U8 = CMP-0096220-1: 3.5V to 65V Synchronous Step-Down Voltage Regulator; Manufacturer: Texas Instruments; Switching Topology: Buck; Output Type: AdjustableProgrammable; SizeZ_mm: 0.7mm; Number Of Outputs: 1; Standoff Height: 0mm
U10 = CMP-0091078-3: Three Buck Converters and 5-V Boost for AWR and IWR Radar Sensors; Manufacturer: Texas Instruments; CompType: IC; AEC Category: Q200; Standoff Height: 0mm; Min Supply Voltage: 3V; TJmax_C: +150°C; Switching Frequency: 4.4-8.8-17.6MHz; Nominal Supply Current: 3uA; TaMax_C: +125°C; Max Supply Voltage: 4V; TaMin_C: -40°C; Number Of Outputs: 4; SizeZ_mm: 1mm; Output Voltage: 0.9-1.9V; AEC Qualified: Yes; AEC Grade: Grade 1; Output Type: AdjustableProgrammable

## Sheet TIDA-010281_RST_SWITCH.SchDoc: BREAKAWAY_SECTION2
size 431 x 279 mm; Date: Not shown in title block; ApprovedBy: Not shown in title block; CheckedBy: Not shown in title block; Author: Not shown in title block; CompanyName: Not shown in title block; DrawnBy: Antony/Bala; Engineer: Not shown in title block; Organization: Not shown in title block; Address1: Not shown in title block; Address2: Not shown in title block; Address3: Not shown in title block; Address4: Not shown in title block; DocumentNumber: 7; Revision: Use project parameter SCH_Rev; SheetNumber: 7; SheetTotal: 10; PageSetup: Record=PageOptions¦CenterHorizontal=True¦CenterVertical=True¦PrintScale=1.00¦XCorrection=1.00¦YCorrection=1.00¦PrintKind=0¦BorderSize=5000000¦LeftOffset=0¦BottomOffset=0¦Orientation=2¦PaperLength=1000¦PaperWidth=1000¦Scale=100¦PaperSource=15¦PrintQuality=600¦MediaType=1¦DitherType=10¦PaperKind=Letter¦PrintScaleMode=1
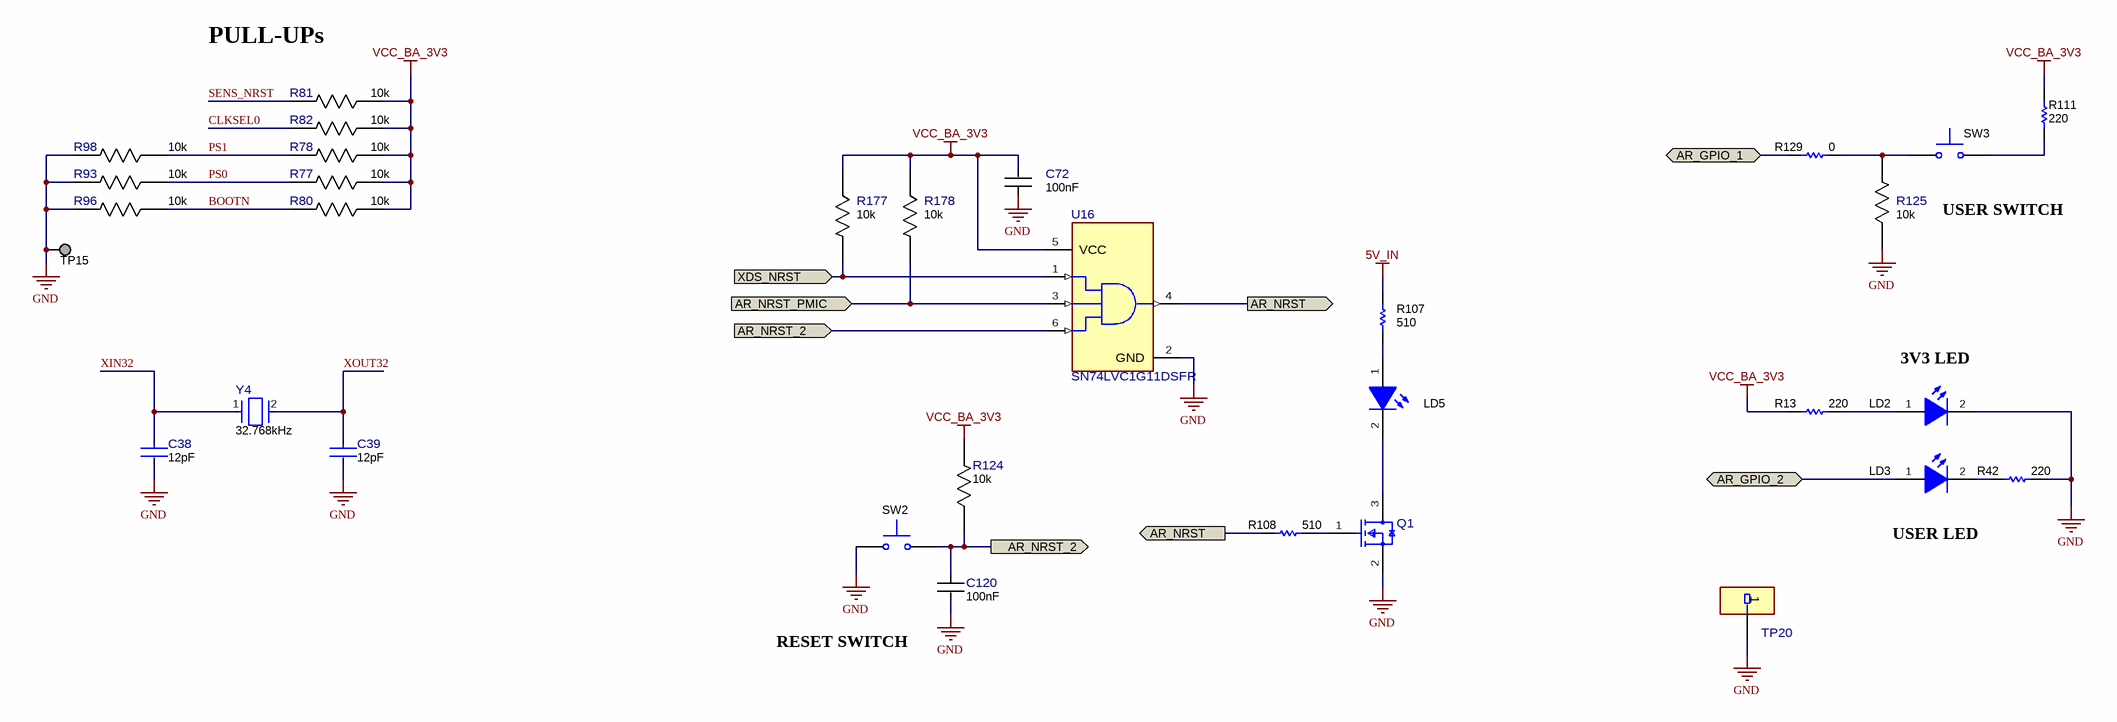
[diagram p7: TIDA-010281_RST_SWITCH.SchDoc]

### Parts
C38  Cap_F: 12pF  [FP-250R05L120JV4T_0201-IPC_C]  (hidden comment: 250R05L120JV4T)
C39  Cap_F: 12pF  [FP-250R05L120JV4T_0201-IPC_C]  (hidden comment: 250R05L120JV4T)
C72  Cap_F: 100nF  [FP-GRM033R6YA104KE14D_0201 (0603 Metric)-IPC_C]  (hidden comment: GRM033R6YA104KE14D)
C120  Cap_F: 100nF  [FP-GRM033R6YA104KE14D_0201 (0603 Metric)-IPC_C]  (hidden comment: GRM033R6YA104KE14D)
LD2  APHHS1005CGCK  [APHHS1005_Green]  (value not drawn)
LD3  APHHS1005CGCK  [APHHS1005_Green]  (value not drawn)
LD5  APHHS1005CGCK  [APHHS1005_Green]  (value not drawn)
Q1  BSS123-7-F  [FP-BSS123-7-F_SOT23-IPC_C]  (value not drawn)
R13  value 220  [0201L]  (hidden comment: RC0201JR-07220RL)
R42  value 220  [0201L]  (hidden comment: RC0201JR-07220RL)
R77  Res_ohm: 10k  [FP-RR0306P-103-D_0201-IPC_C]  (hidden comment: RR0306P-103-D)
R78  Res_ohm: 10k  [FP-RR0306P-103-D_0201-IPC_C]  (hidden comment: RR0306P-103-D)
R80  Res_ohm: 10k  [FP-RR0306P-103-D_0201-IPC_C]  (hidden comment: RR0306P-103-D)
R81  Res_ohm: 10k  [FP-RR0306P-103-D_0201-IPC_C]  (hidden comment: RR0306P-103-D)
R82  Res_ohm: 10k  [FP-RR0306P-103-D_0201-IPC_C]  (hidden comment: RR0306P-103-D)
R93  Res_ohm: 10k  [FP-RR0306P-103-D_0201-IPC_C]  (hidden comment: RR0306P-103-D)
R96  Res_ohm: 10k  [FP-RR0306P-103-D_0201-IPC_C]  (hidden comment: RR0306P-103-D)
R98  Res_ohm: 10k  [FP-RR0306P-103-D_0201-IPC_C]  (hidden comment: RR0306P-103-D)
R107  value 510  [0201L]  (hidden comment: RC0201JR-07510RL)
R108  value 510  [0201L]  (hidden comment: RC0201JR-07510RL)
R111  value 220  [0201L]  (hidden comment: RC0201JR-07220RL)
R124  Res_ohm: 10k  [FP-RR0306P-103-D_0201-IPC_C]  (hidden comment: RR0306P-103-D)
R125  Res_ohm: 10k  [FP-RR0306P-103-D_0201-IPC_C]  (hidden comment: RR0306P-103-D)
R129  Res_ohm: 0  [FP-RC0201JR-070RL_0201 (0603 Metric)-IPC_C]  (hidden comment: RC0201JR-070RL)
R177  Res_ohm: 10k  [FP-RR0306P-103-D_0201-IPC_C]  (hidden comment: RR0306P-103-D)
R178  Res_ohm: 10k  [FP-RR0306P-103-D_0201-IPC_C]  (hidden comment: RR0306P-103-D)
SW2  B3U-1000P  [SW_B3U-1000P]  (value not drawn)
SW3  B3U-1000P  [SW_B3U-1000P]  (value not drawn)
TP15  TESTPOINT  [TP_25MIL-SMT]  (value not drawn)  (no BOM)
TP20  4953  [FP-4953_HDR1-MFG]  (value not drawn)
U16  SN74LVC1G11DSFR  [DSF0006A-MFG]
Y4  Frequency_Fixed: 32.768kHz  [FP-ABS05W-32.768KHZ-D-2-T_XTAL_SMT_1MM6_1MM0-MFG]  (hidden comment: ABS05W-32.768KHZ-D-2-T)

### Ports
AR_GPIO_1 (bidir), AR_GPIO_2 (bidir), AR_NRST (out), AR_NRST_2 (in), AR_NRST_2 (out), AR_NRST_PMIC (in), XDS_NRST (in)

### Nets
5V_IN: R107.1
GND: C38.2 C39.2 C72.1 C120.2 LD2.2(K) Q1.2(S) R42.2 R93.2 R96.2 R98.2 R125.1 SW2.2 TP15.1 TP20.1 U16.2(GND)
VCC_BA_3V3: C72.2 R13.1 R77.1 R78.1 R80.1 R81.1 R82.1 R111.2 R124.2 R177.1 R178.1 U16.5(VCC)
AR_GPIO_1: R129.2 ; port AR_GPIO_1
AR_GPIO_2: LD3.1(A) ; port AR_GPIO_2
AR_NRST: R108.1 U16.4(Y) ; port AR_NRST
AR_NRST_2: C120.1 R124.1 SW2.1 U16.6(C) ; port AR_NRST_2
AR_NRST_PMIC: R178.2 U16.3(B) ; port AR_NRST_PMIC
BOOTN: R80.2 R96.1
CLKSEL0: R82.2
PS0: R77.2 R93.1
PS1: R78.2 R98.1
SENS_NRST: R81.2
XDS_NRST: R177.2 U16.1(A) ; port XDS_NRST
XIN32: C38.1 Y4.1
XOUT32: C39.1 Y4.2
NetLD2_1: LD2.1(A) R13.2
NetLD3_2: LD3.2(K) R42.1
NetLD5_1: LD5.1(A) R107.2
NetLD5_2: LD5.2(K) Q1.3(D)
NetQ1_1: Q1.1(G) R108.2
NetR111_1: R111.1 SW3.2
NetR125_2: R125.2 R129.1 SW3.1

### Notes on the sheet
- PULL-UPs
- (near SW3) USER SWITCH
- (near LD2) 3V3 LED
- USER LED
- RESET SWITCH

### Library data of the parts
C38 C39 = CMP-0087190-1: CAP CER 12PF 25V C0G/NP0 0201; Manufacturer: Johanson Technology Inc.; AEC Grade: Grade 1; AEC Qualified: Yes; SizeZ_mm: 0.33mm; Symbol Name: SYM-250R05L120JV4T; TempCo: 30ppm/°C; Tolerance_%: 5%
C72 C120 = CMP-0086440-1: Cap Ceramic 0.1uF 35V X5R 10% Pad SMD 0201 85C T/R; Manufacturer: Murata Electronics North America; AEC Qualified: No; SizeZ_mm: 0.33mm; Symbol Name: SYM-GRM033R6YA104KE14D; TempCo: 15%
LD2 LD3 LD5 = CMP-0067682-2: as LD1 on sheet TIDA-010281_PMIC_BUCK
Q1 = CMP-0087176-1: MOSFET N-CH 100V 170MA SOT23-3; Manufacturer: Diodes Incorporated; AEC Qualified: No; ChMode: False; Rdson45_ohm: 6; SizeZ_mm: 1.1mm; Vgs_V: 20V
R13 R42 R111 = CMP-0027072-1: RES, 220, 5%, 0.05 W, 0201; Manufacturer: Yageo America; AEC Category: Q200; AEC Qualified: N; EIA_Code: E24; Power_W: 50mW; SizeArea_mm2: 0.18; SizeX_mm: 0.6; SizeY_mm: 0.3; SizeZ_mm: 0.26; TempCo: 200 ppm/C; U/M: EA; Value2: 0.05W; Value_Code: 220R; VDC_V: 25V
R77 R78 R80-R82 R93 R96 R98 R124 R125 R177 R178 = CMP-0088002-1: 10 kOhms ±0.5% 0.05W, 1/20W Chip Resistor 0201 (0603 Metric)  Thin Film; Manufacturer: Susumu; AEC Qualified: No; Power_W: 50mW; SizeZ_mm: 0.26mm; Symbol Name: SYM-RR0306P-103-D; TempCo: 25ppm/°C; VDC_V: 15V
R107 R108 = CMP-0027137-1: as R105 on sheet TIDA-010281_PMIC_BUCK
R129 = CMP-0086442-2: as R118 on sheet TIDA-010281_PMIC_BUCK
SW2 SW3 = CMP-0002150-2: SWITCH TACTILE SPST-NO 0.05A 12V; Manufacturer: Omron Electronic Components; CurrentRating_mA: 50A; PositionCount: 1; SwitchFunction: Off-Mom
TP15 = CMP-0078143-3: TEST POINT.  No entry in BOM.
TP20 = CMP-0086474-1: PC Test Point, Loop Brass, Tin Plating 0.047" (1.19mm) Hole Diameter Mounting Type; Manufacturer: Keystone Electronics
U16 = CMP-0087998-2: AND Gate IC 1 Channel  6-SON (1x1); Manufacturer: Texas Instruments; TJmax_C: +150°C; PositionCount: 1; Number Of Inputs: 3; SizeZ_mm: 0.4mm; TaMax_C: +125°C; Max Supply Voltage: 5.5V; Min Supply Voltage: 1.65V; Standoff Height: 0mm; AEC Qualified: No; TaMin_C: -40°C; AEC Category: Q200
Y4 = CMP-0088006-1: CRYSTAL 32.768KHZ 4PF SMD; Manufacturer: Abracon LLC; AEC Qualified: No; Frequency Tolerance: 20ppm; SizeZ_mm: 0.5mm

## Sheet TIDA-010281_TABLEOFCONTENTS.SchDoc: TABLE_OF_CONTENTS
size 431 x 279 mm; Date: Not shown in title block; ApprovedBy: Not shown in title block; CheckedBy: Not shown in title block; Author: Not shown in title block; CompanyName: Not shown in title block; DrawnBy: Antony/Bala; Engineer: Not shown in title block; Organization: Not shown in title block; Address1: Not shown in title block; Address2: Not shown in title block; Address3: Not shown in title block; Address4: Not shown in title block; DocumentNumber: 2; Revision: Use project parameter SCH_Rev; SheetNumber: 2; SheetTotal: 10; PageSetup: Record=PageOptions¦CenterHorizontal=True¦CenterVertical=True¦PrintScale=1.00¦XCorrection=1.00¦YCorrection=1.00¦PrintKind=0¦BorderSize=5000000¦LeftOffset=0¦BottomOffset=0¦Orientation=2¦PaperLength=1000¦PaperWidth=1000¦Scale=100¦PaperSource=15¦PrintQuality=600¦MediaType=1¦DitherType=10¦PaperKind=Letter¦PrintScaleMode=1
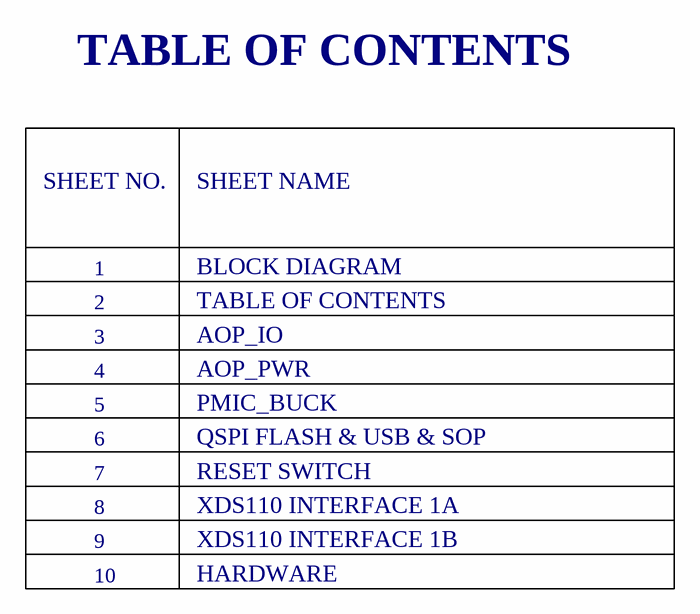
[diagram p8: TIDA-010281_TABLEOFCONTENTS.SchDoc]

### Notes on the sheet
- TABLE OF CONTENTS
- SHEET NO.
- SHEET NAME
- 1
- 2
- 3
- BLOCK DIAGRAM
- AOP_IO
- 4
- 5
- AOP_PWR
- PMIC_BUCK
- 7
- 8
- 6
- QSPI FLASH & USB & SOP
- RESET SWITCH
- XDS110 INTERFACE 1A
- 9
- 10
- XDS110 INTERFACE 1B
- HARDWARE

## Sheet TIDA-010281_XDS110_interface_1A.SchDoc
size 431 x 279 mm; Date: Not shown in title block; ApprovedBy: Not shown in title block; CheckedBy: Not shown in title block; Author: Not shown in title block; CompanyName: Not shown in title block; Engineer: Not shown in title block; Organization: Not shown in title block; Address1: Not shown in title block; Address2: Not shown in title block; Address3: Not shown in title block; Address4: Not shown in title block; DocumentNumber: 8; Revision: Use project parameter SCH_Rev; SheetNumber: 8; SheetTotal: 10; PageSetup: Record=PageOptions¦CenterHorizontal=True¦CenterVertical=True¦PrintScale=1.00¦XCorrection=1.00¦YCorrection=1.00¦PrintKind=0¦BorderSize=5000000¦LeftOffset=0¦BottomOffset=0¦Orientation=2¦PaperLength=1000¦PaperWidth=1000¦Scale=100¦PaperSource=15¦PrintQuality=600¦MediaType=1¦DitherType=10¦PaperKind=Letter¦PrintScaleMode=1
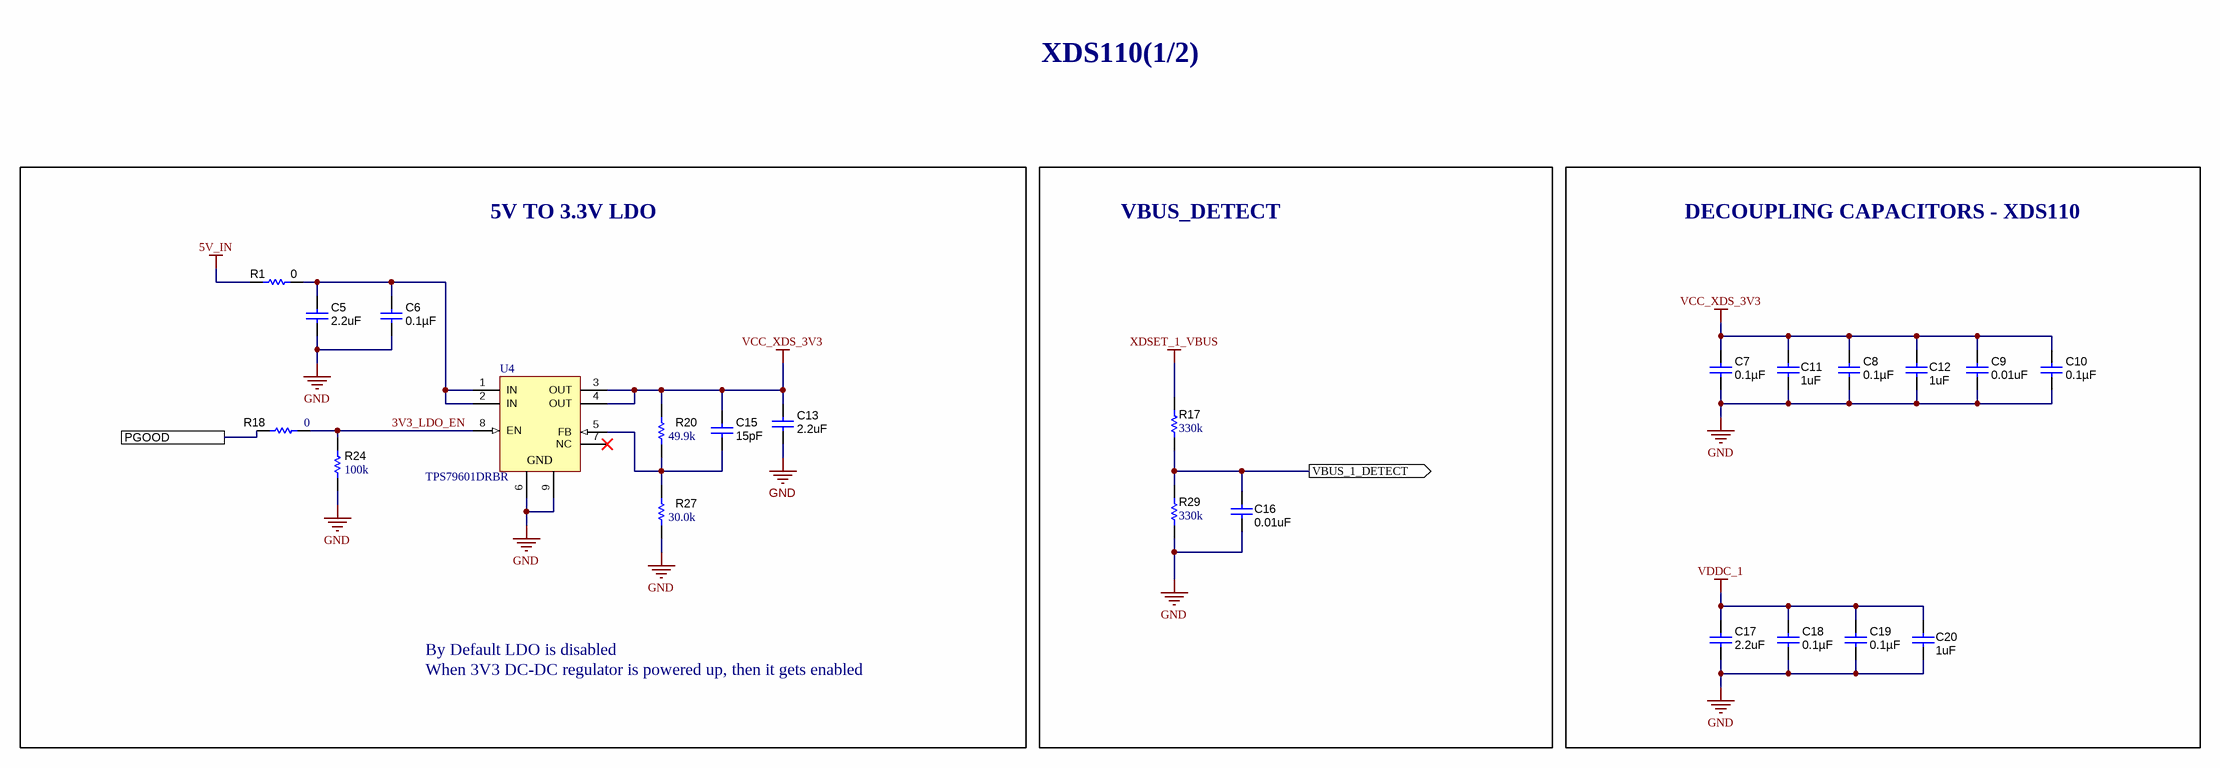
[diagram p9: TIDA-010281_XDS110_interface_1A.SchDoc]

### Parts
C5  ValueDisplayed: 2.2uF  [0402_065L]  (hidden comment: C1005X7S1A225K050BC)
C6  ValueDisplayed: 0.1µF  [0402L]  (hidden comment: C0402C104K8RACTU)
C7  ValueDisplayed: 0.1µF  [0402L]  (hidden comment: C0402C104K8RACTU)
C8  ValueDisplayed: 0.1µF  [0402L]  (hidden comment: C0402C104K8RACTU)
C9  ValueDisplayed: 0.01uF  [0402L]  (hidden comment: GCM155R71E103KA37D)
C10  ValueDisplayed: 0.1µF  [0402L]  (hidden comment: C0402C104K8RACTU)
C11  ValueDisplayed: 1uF  [0402L]  (hidden comment: GRT155C81A105KE01D)
C12  ValueDisplayed: 1uF  [0402L]  (hidden comment: GRT155C81A105KE01D)
C13  ValueDisplayed: 2.2uF  [0402_065L]  (hidden comment: C1005X7S1A225K050BC)
C15  ValueDisplayed: 15pF  [0402L]  (hidden comment: 04025A150FAT2A)
C16  ValueDisplayed: 0.01uF  [0402L]  (hidden comment: GCM155R71E103KA37D)
C17  ValueDisplayed: 2.2uF  [0402_065L]  (hidden comment: C1005X7S1A225K050BC)
C18  ValueDisplayed: 0.1µF  [0402L]  (hidden comment: C0402C104K8RACTU)
C19  ValueDisplayed: 0.1µF  [0402L]  (hidden comment: C0402C104K8RACTU)
C20  ValueDisplayed: 1uF  [0402L]  (hidden comment: GRT155C81A105KE01D)
R1  ValueDisplayed: 0  [0603]  (hidden comment: MCT06030Z0000ZP500)
R17  ValueDisplayed: 330k  [0402L]  (hidden comment: CRCW0402330KFKED)
R18  ValueDisplayed: 0  [0402]  (hidden comment: ERJ-2GE0R00X)
R20  ValueDisplayed: 49.9k  [0402L]  (hidden comment: CRCW040249K9FKED)
R24  ValueDisplayed: 100k  [0402L]  (hidden comment: CRCW0402100KFKED)
R27  ValueDisplayed: 30.0k  [0402L]  (hidden comment: CRCW040230K0FKED)
R29  ValueDisplayed: 330k  [0402L]  (hidden comment: CRCW0402330KFKED)
U4  TPS79601DRBR  [DRB0008B]

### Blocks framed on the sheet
5V TO 3.3V LDO: C5 C6 C13 C15 R1 R18 R20 R24 R27 U4
VBUS_DETECT: C16 R17 R29
DECOUPLING CAPACITORS - XDS110: C7-C12 C17-C20

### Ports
PGOOD, VBUS_1_DETECT (out)

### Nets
5V_IN: R1.1
GND: C5.2 C6.2 C7.1 C8.1 C9.2 C10.1 C11.2 C12.2 C13.1 C16.1 C17.1 C18.1 C19.1 C20.2 R24.1 R27.1 R29.1 U4.6(GND) U4.9(GND)
VCC_XDS_3V3: C7.2 C8.2 C9.1 C10.2 C11.1 C12.1 C13.2 C15.2 R20.2 U4.3(OUT) U4.4(OUT)
VDDC_1: C17.2 C18.2 C19.2 C20.1
XDSET_1_VBUS: R17.2
3V3_LDO_EN: R18.2 R24.2 U4.8(EN)
PGOOD: R18.1 ; port PGOOD
VBUS_1_DETECT: C16.2 R17.1 R29.2 ; port VBUS_1_DETECT
NetC5_1: C5.1 C6.1 R1.2 U4.1(IN) U4.2(IN)
NetC15_1: C15.1 R20.1 R27.2 U4.5(FB)

Not connected (* = marked no-connect by the designer): U4 7(NC)*

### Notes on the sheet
- XDS110(1/2)
- By Default LDO is disabled
- When 3V3 DC-DC regulator is powered up, then it gets enabled

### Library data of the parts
C5 C13 C17 = CMP-0006302-2: CAP, CERM, 2.2 uF, 10 V, +/- 10%, X7S, 0402; Manufacturer: TDK; TaMin_C: -55°C; ESR_ohm: 5.925m; Polarized: N; SizeAreaWB_mm2: 3; Value1: 0.005925 ohm; U/M: EA; Value: 2.2uF; TaMax_C: 125°C; SizeZ_mm: 0.65; SizeX_mm: 1; SizeY_mm: 0.5; Cap_Case: 0402_065; Value2: 10V; CompType: Capacitor; Cap_F: 2.2µF; IRMS_A: 2.05591A; AEC Category: Q200
C6 = CMP-0078241-1: CAP, CERM, 0.1 µF, 10 V,+/- 10%, X7R, 0402; Manufacturer: Kemet; TaMin_C: -55°C; Polarized: N; SizeAreaWB_mm2: 3; U/M: EA; Value: 0.1uF; TaMax_C: 125°C; SizeZ_mm: 0.6; SizeX_mm: 1; SizeY_mm: 0.5; Cap_Case: 0402; Value2: 10V; Cap_F: 100nF; AEC Category: Q200
C7 C8 C10 C18 C19 = CMP-0078241-1: CAP, CERM, 0.1 µF, 10 V,+/- 10%, X7R, 0402; Manufacturer: Kemet; TaMin_C: -55°C; Polarized: N; SizeAreaWB_mm2: 3; U/M: EA; Value: 0.1uF; TaMax_C: 125°C; SizeZ_mm: 0.6; SizeX_mm: 1; SizeY_mm: 0.5; Cap_Case: 0402; Value2: 10V; CompType: Capacitor; Cap_F: 100nF; AEC Category: Q200
C9 C16 = CMP-0006352-2: CAP, CERM, 0.01 uF, 25 V, +/- 10%, X7R, 0402; Manufacturer: MuRata; TaMin_C: -55°C; Polarized: N; SizeAreaWB_mm2: 3; Value1: Unknown; U/M: EA; Value: 0.01uF; TaMax_C: 125°C; SizeZ_mm: 0.6; SizeX_mm: 1; SizeY_mm: 0.5; Cap_Case: 0402; Value2: 25V; CompType: Capacitor; Cap_F: 10nF; AEC Category: Q200
C11 C12 C20 = CMP-0006272-2: CAP, CERM, 1 uF, 10 V, +/- 10%, X6S, 0402; Manufacturer: TDK; Polarized: N; Value: 1uF; U/M: EA; Cap_F: 1µF; Value1: Unknown; VDC_V: 16V; TempCo: X5R; TaMin_C: -55°C; TaMax_C: 85°C; Cap_Case: 0402; SizeArea_mm2: 0.5; SizeAreaWB_mm2: 3; SizeX_mm: 1; SizeZ_mm: 0.6; AEC Category: Q200
C15 = CMP-0078217-1: CAP, CERM, 15 pF, 50 V,+/- 1%, C0G/NP0, 0402; Manufacturer: AVX; TaMin_C: -55°C; Polarized: N; Green_Lifecycle: Not Set; SizeAreaWB_mm2: 3; Green_REACh: Incomplete; U/M: EA; Value: 15pF; TaMax_C: 125°C; SizeZ_mm: 0.6; SizeX_mm: 1; SizeY_mm: 0.5; Cap_Case: 0402; Value2: 50V; AEC Category: Q200
R1 = CMP-0025884-3: RES, 0, 5%, 0.125 W, 0603; Manufacturer: Vishay/Beyschlag; Power_W: 125mW; TempCo: ppm/C; Value_Code: 0000; U/M: EA; Value: 0; EIA_Code: E24; SizeX_mm: 1.6; SizeY_mm: 0.8; SizeZ_mm: 1; Value2: 0.125W; SizeArea_mm2: 1.28; AEC Qualified: N; AEC Category: Q200
R17 R29 = CMP-0078210-2: RES, 330 k, 1%, 0.063 W, AEC-Q200 Grade 0, 0402; Manufacturer: Vishay-Dale; SizeArea_mm2: 0.5; AEC Qualified: Y; AEC Category: Q200; Value: 330k; SizeZ_mm: 0.6; TempCo: 100 ppm/C; AEC Grade: 0; Power_W: 63mW; VDC_V: 50V; Value2: 0.063W; SizeX_mm: 1
R18 = CMP-0026992-3: as R92 on sheet TIDA-010281_PMIC_BUCK
R20 = CMP-0026403-2: RES, 49.9 k, 1%, 0.063 W, AEC-Q200 Grade 0, 0402; Manufacturer: Vishay-Dale; Power_W: 63mW; TempCo: 100 ppm/C; Value_Code: 49k9; Value: 49.9k; EIA_Code: E96; SizeX_mm: 1; SizeY_mm: 0.5; SizeZ_mm: 0.6; Value2: 0.063W; AEC Qualified: Y; VDC_V: 50V; AEC Category: Q200; AEC Grade: 0
R24 = CMP-0025950-3: as R112 on sheet TIDA-010281_PMIC_BUCK
R27 = CMP-0078244-2: RES, 30.0 k, 1%, 0.063 W, AEC-Q200 Grade 0, 0402; Manufacturer: Vishay-Dale; Power_W: 63mW; Green_Lifecycle: Active; TempCo: 100 ppm/C; Value_Code: 30k0; Green_REACh: Passed; Value: 30.0k; Res_ohm: 30k; SizeX_mm: 1; SizeY_mm: 0.5; SizeZ_mm: 0.6; Value2: 0.063W; AEC Qualified: Y; VDC_V: 50V; AEC Grade: 0; AEC Category: Q200
U4 = CMP-0036402-3: Single Output High PSRR LDO, 1 A, Adjustable 1.2 to 5.5 V Output, 2.7 to 5.5 V Input, 8-pin SON (DRB), -40 to 125 degC, Green (RoHS & no Sb/Br); Manufacturer: Texas Instruments; Vin(Min)(V): 2.7; Vout Adj(Max)(V): 5.5; Vout Adj(Min)(V): 1.2; Accuracy(%): 2; SubFamily: Single Channel LDO; Iq(Typ)(mA): 0.26; Vdo(Typ)(mV): 250; Iout(Max)(A): 1; AEC Category: Q200; AEC Qualified: N; CompType: IC; SizeAreaWB_mm2: 16.0; SizeArea_mm2: 9.0; SizeX_mm: 3.0; SizeZ_mm: 1.0

## Sheet TIDA-010281_XDS110_interface_1B.SchDoc
size 431 x 279 mm; Date: Not shown in title block; ApprovedBy: Not shown in title block; CheckedBy: Not shown in title block; Author: Not shown in title block; CompanyName: Not shown in title block; Engineer: Not shown in title block; Organization: Not shown in title block; Address1: Not shown in title block; Address2: Not shown in title block; Address3: Not shown in title block; Address4: Not shown in title block; DocumentNumber: 9; Revision: Use project parameter SCH_Rev; SheetNumber: 9; SheetTotal: 10; PageSetup: Record=PageOptions¦CenterHorizontal=True¦CenterVertical=True¦PrintScale=1.00¦XCorrection=1.00¦YCorrection=1.00¦PrintKind=0¦BorderSize=5000000¦LeftOffset=0¦BottomOffset=0¦Orientation=2¦PaperLength=1000¦PaperWidth=1000¦Scale=100¦PaperSource=15¦PrintQuality=600¦MediaType=1¦DitherType=10¦PaperKind=Letter¦PrintScaleMode=1
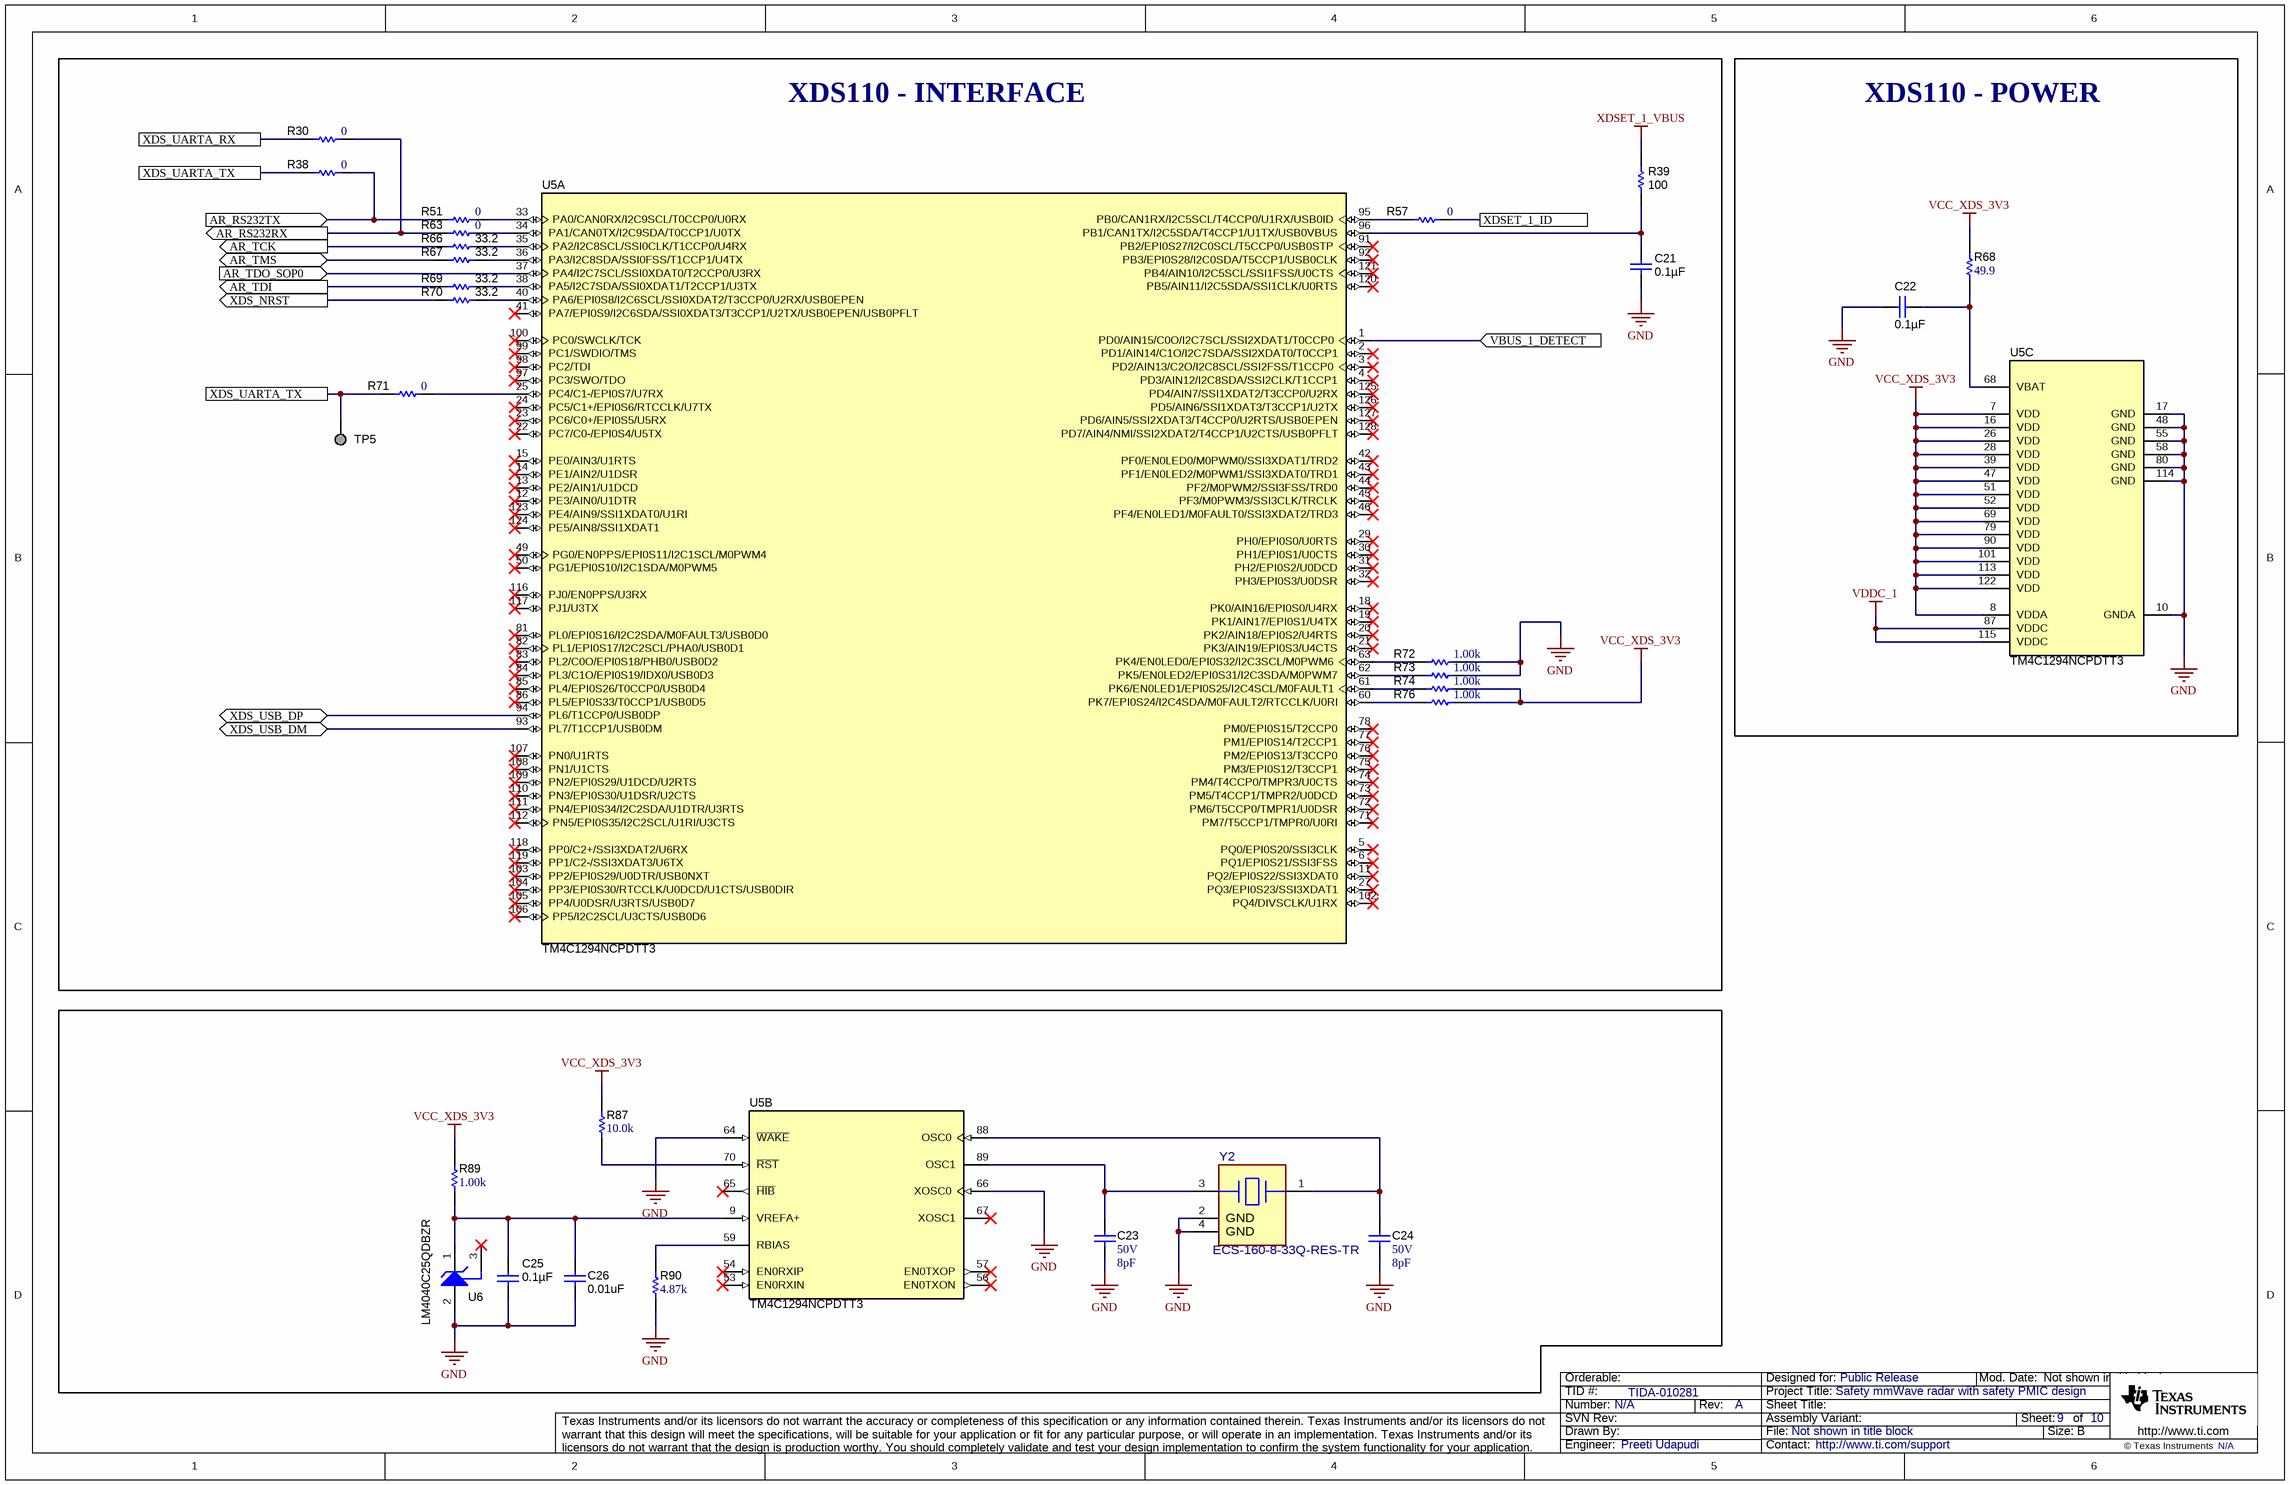
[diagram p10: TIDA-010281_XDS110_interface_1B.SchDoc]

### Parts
C21  ValueDisplayed: 0.1µF  [0402L]  (hidden comment: C0402C104K8RACTU)
C22  ValueDisplayed: 0.1µF  [0402L]  (hidden comment: C0402C104K8RACTU)
C23  VDC_V: 50V  ValueDisplayed: 8pF  [0402L]  (hidden comment: CC0402DRNPO9BN8R0)
C24  VDC_V: 50V  ValueDisplayed: 8pF  [0402L]  (hidden comment: CC0402DRNPO9BN8R0)
C25  ValueDisplayed: 0.1µF  [0402L]  (hidden comment: C0402C104K8RACTU)
C26  ValueDisplayed: 0.01uF  [0402L]  (hidden comment: GCM155R71E103KA37D)
R30  ValueDisplayed: 0  [0402]  (hidden comment: ERJ-2GE0R00X)
R38  ValueDisplayed: 0  [0402]  (hidden comment: ERJ-2GE0R00X)
R39  ValueDisplayed: 100  [0402L]  (hidden comment: ERJ-2GEJ101X)
R51  ValueDisplayed: 0  [0402]  (hidden comment: ERJ-2GE0R00X)
R57  ValueDisplayed: 0  [0402]  (hidden comment: ERJ-2GE0R00X)
R63  ValueDisplayed: 0  [0402]  (hidden comment: ERJ-2GE0R00X)
R66  ValueDisplayed: 33.2  [0201_Silk]  (hidden comment: CRCW020133R2FNED)
R67  ValueDisplayed: 33.2  [0201_Silk]  (hidden comment: CRCW020133R2FNED)
R68  ValueDisplayed: 49.9  [0402L]  (hidden comment: CRCW040249R9FKED)
R69  ValueDisplayed: 33.2  [0201_Silk]  (hidden comment: CRCW020133R2FNED)
R70  ValueDisplayed: 33.2  [0201_Silk]  (hidden comment: CRCW020133R2FNED)
R71  ValueDisplayed: 0  [0201_Silk]  (hidden comment: CRCW02010000Z0ED)
R72  ValueDisplayed: 1.00k  [0402L]  (hidden comment: CRCW04021K00FKED)
R73  ValueDisplayed: 1.00k  [0402L]  (hidden comment: CRCW04021K00FKED)
R74  ValueDisplayed: 1.00k  [0402L]  (hidden comment: CRCW04021K00FKED)
R76  ValueDisplayed: 1.00k  [0402L]  (hidden comment: CRCW04021K00FKED)
R87  ValueDisplayed: 10.0k  [0402L]  (hidden comment: CRCW040210K0FKED)
R89  ValueDisplayed: 1.00k  [0402L]  (hidden comment: CRCW04021K00FKED)
R90  ValueDisplayed: 4.87k  [0402L]  (hidden comment: CRCW04024K87FKED)
TP5  TESTPOINT  [TP_VIA_060RND040]  (value not drawn)  (no BOM)
U5  TM4C1294NCPDTT3  [PDT0128A]  (parts A,B,C of 3)
U6  LM4040C25QDBZR  [DBZ0003A_N]
Y2  ECS-160-8-33Q-RES-TR  [FP-ECS-160-8-33Q-RES-TR_SMT4_3MM2_2MM5-MFG]

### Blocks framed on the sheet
XDS110 - INTERFACE: C21 R30 R38 R39 R51 R57 R63 R66 R67 R69-R74 R76 TP5 U5
XDS110 - POWER: C22 R68 U5

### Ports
AR_RS232RX (out), AR_RS232TX (in), AR_TCK (out), AR_TDI (out), AR_TDO_SOP0 (in), AR_TMS (bidir), VBUS_1_DETECT (in), XDS_NRST (out), XDS_UARTA_RX, XDS_UARTA_TX, XDS_USB_DM (bidir), XDS_USB_DP (bidir), XDSET_1_ID

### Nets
GND: C21.2 C22.1 C23.1 C24.1 C25.1 C26.1 R72.2 R73.2 R90.1 U5.10(GNDA) U5.17(GND) U5.48(GND) U5.55(GND) U5.58(GND) U5.64(~{WAKE}) U5.66(XOSC0) U5.80(GND) U5.114(GND) U6.2(ANODE) Y2.2(GND) Y2.4(GND)
VCC_XDS_3V3: R68.1 R74.2 R76.2 R87.2 R89.2 U5.7(VDD) U5.8(VDDA) U5.16(VDD) U5.26(VDD) U5.28(VDD) U5.39(VDD) U5.47(VDD) U5.51(VDD) U5.52(VDD) U5.69(VDD) U5.79(VDD) U5.90(VDD) U5.101(VDD) U5.113(VDD) U5.122(VDD)
VDDC_1: U5.87(VDDC) U5.115(VDDC)
XDSET_1_VBUS: R39.2
AR_RS232RX: R30.2 R63.1 ; port AR_RS232RX
AR_RS232TX: R38.2 R51.1 ; port AR_RS232TX
AR_TCK: R66.2 ; port AR_TCK
AR_TDI: R69.2 ; port AR_TDI
AR_TDO_SOP0: U5.37(PA4/I2C7SCL/SSI0XDAT0/T2CCP0/U3RX) ; port AR_TDO_SOP0
AR_TMS: R67.2 ; port AR_TMS
USB_DM: U5.93(PL7/T1CCP1/USB0DM) ; port XDS_USB_DM
USB_DP: U5.94(PL6/T1CCP0/USB0DP) ; port XDS_USB_DP
VBUS_1_DETECT: U5.1(PD0/AIN15/C0O/I2C7SCL/SSI2XDAT1/T0CCP0) ; port VBUS_1_DETECT
XDS_NRST: R70.2 ; port XDS_NRST
XDS_UARTA_RX: R30.1 ; port XDS_UARTA_RX
XDS_UARTA_TX: R38.1 R71.1 TP5.1 ; port XDS_UARTA_TX
XDSET_1_ID: R57.2 ; port XDSET_1_ID
NetC21_1: C21.1 R39.1 U5.96(PB1/CAN1TX/I2C5SDA/T4CCP1/U1TX/USB0VBUS)
NetC22_2: C22.2 R68.2 U5.68(VBAT)
NetC23_2: C23.2 U5.89(OSC1) Y2.3(OUT/IN)
NetC24_2: C24.2 U5.88(OSC0) Y2.1(IN/OUT)
NetC25_2: C25.2 C26.2 R89.1 U5.9(VREFA+) U6.1(CATHODE)
NetR51_2: R51.2 U5.33(PA0/CAN0RX/I2C9SCL/T0CCP0/U0RX)
NetR57_1: R57.1 U5.95(PB0/CAN1RX/I2C5SCL/T4CCP0/U1RX/USB0ID)
NetR63_2: R63.2 U5.34(PA1/CAN0TX/I2C9SDA/T0CCP1/U0TX)
NetR66_1: R66.1 U5.35(PA2/I2C8SCL/SSI0CLK/T1CCP0/U4RX)
NetR67_1: R67.1 U5.36(PA3/I2C8SDA/SSI0FSS/T1CCP1/U4TX)
NetR69_1: R69.1 U5.38(PA5/I2C7SDA/SSI0XDAT1/T2CCP1/U3TX)
NetR70_1: R70.1 U5.40(PA6/EPI0S8/I2C6SCL/SSI0XDAT2/T3CCP0/U2RX/USB0EPEN)
NetR71_2: R71.2 U5.25(PC4/C1-/EPI0S7/U7RX)
NetR72_1: R72.1 U5.63(PK4/EN0LED0/EPI0S32/I2C3SCL/M0PWM6)
NetR73_1: R73.1 U5.62(PK5/EN0LED2/EPI0S31/I2C3SDA/M0PWM7)
NetR74_1: R74.1 U5.61(PK6/EN0LED1/EPI0S25/I2C4SCL/M0FAULT1)
NetR76_1: R76.1 U5.60(PK7/EPI0S24/I2C4SDA/M0FAULT2/RTCCLK/U0RI)
NetR87_1: R87.1 U5.70(~{RST})
NetR90_2: R90.2 U5.59(RBIAS)

Not connected (* = marked no-connect by the designer): U5 2(PD1/AIN14/C1O/I2C7SDA/SSI2XDAT0/T0CCP1)* 3(PD2/AIN13/C2O/I2C8SCL/SSI2FSS/T1CCP0)* 4(PD3/AIN12/I2C8SDA/SSI2CLK/T1CCP1)* 5(PQ0/EPI0S20/SSI3CLK)* 6(PQ1/EPI0S21/SSI3FSS)* 11(PQ2/EPI0S22/SSI3XDAT0)* 12(PE3/AIN0/U1DTR)* 13(PE2/AIN1/U1DCD)* 14(PE1/AIN2/U1DSR)* 15(PE0/AIN3/U1RTS)* 18(PK0/AIN16/EPI0S0/U4RX)* 19(PK1/AIN17/EPI0S1/U4TX)* 20(PK2/AIN18/EPI0S2/U4RTS)* 21(PK3/AIN19/EPI0S3/U4CTS)* 22(PC7/C0-/EPI0S4/U5TX)* 23(PC6/C0+/EPI0S5/U5RX)* 24(PC5/C1+/EPI0S6/RTCCLK/U7TX)* 27(PQ3/EPI0S23/SSI3XDAT1)* 29(PH0/EPI0S0/U0RTS)* 30(PH1/EPI0S1/U0CTS)* 31(PH2/EPI0S2/U0DCD)* 32(PH3/EPI0S3/U0DSR)* 41(PA7/EPI0S9/I2C6SDA/SSI0XDAT3/T3CCP1/U2TX/USB0EPEN/USB0PFLT)* 42(PF0/EN0LED0/M0PWM0/SSI3XDAT1/TRD2)* 43(PF1/EN0LED2/M0PWM1/SSI3XDAT0/TRD1)* 44(PF2/M0PWM2/SSI3FSS/TRD0)* 45(PF3/M0PWM3/SSI3CLK/TRCLK)* 46(PF4/EN0LED1/M0FAULT0/SSI3XDAT2/TRD3)* 49(PG0/EN0PPS/EPI0S11/I2C1SCL/M0PWM4)* 50(PG1/EPI0S10/I2C1SDA/M0PWM5)* 53(EN0RXIN)* 54(EN0RXIP)* 56(EN0TXON)* 57(EN0TXOP)* 65(~{HIB})* 67(XOSC1)* 71(PM7/T5CCP1/TMPR0/U0RI)* 72(PM6/T5CCP0/TMPR1/U0DSR)* 73(PM5/T4CCP1/TMPR2/U0DCD)* 74(PM4/T4CCP0/TMPR3/U0CTS)* 75(PM3/EPI0S12/T3CCP1)* 76(PM2/EPI0S13/T3CCP0)* 77(PM1/EPI0S14/T2CCP1)* 78(PM0/EPI0S15/T2CCP0)* 81(PL0/EPI0S16/I2C2SDA/M0FAULT3/USB0D0)* 82(PL1/EPI0S17/I2C2SCL/PHA0/USB0D1)* 83(PL2/C0O/EPI0S18/PHB0/USB0D2)* 84(PL3/C1O/EPI0S19/IDX0/USB0D3)* 85(PL4/EPI0S26/T0CCP0/USB0D4)* 86(PL5/EPI0S33/T0CCP1/USB0D5)* 91(PB2/EPI0S27/I2C0SCL/T5CCP0/USB0STP)* 92(PB3/EPI0S28/I2C0SDA/T5CCP1/USB0CLK)* 97(PC3/SWO/TDO)* 98(PC2/TDI)* 99(PC1/SWDIO/TMS)* 100(PC0/SWCLK/TCK)* 102(PQ4/DIVSCLK/U1RX)* 103(PP2/EPI0S29/U0DTR/USB0NXT)* 104(PP3/EPI0S30/RTCCLK/U0DCD/U1CTS/USB0DIR)* 105(PP4/U0DSR/U3RTS/USB0D7)* 106(PP5/I2C2SCL/U3CTS/USB0D6)* 107(PN0/U1RTS)* 108(PN1/U1CTS)* 109(PN2/EPI0S29/U1DCD/U2RTS)* 110(PN3/EPI0S30/U1DSR/U2CTS)* 111(PN4/EPI0S34/I2C2SDA/U1DTR/U3RTS)* 112(PN5/EPI0S35/I2C2SCL/U1RI/U3CTS)* 116(PJ0/EN0PPS/U3RX)* 117(PJ1/U3TX)* 118(PP0/C2+/SSI3XDAT2/U6RX)* 119(PP1/C2-/SSI3XDAT3/U6TX)* 120(PB5/AIN11/I2C5SDA/SSI1CLK/U0RTS)* 121(PB4/AIN10/I2C5SCL/SSI1FSS/U0CTS)* 123(PE4/AIN9/SSI1XDAT0/U1RI)* 124(PE5/AIN8/SSI1XDAT1)* 125(PD4/AIN7/SSI1XDAT2/T3CCP0/U2RX)* 126(PD5/AIN6/SSI1XDAT3/T3CCP1/U2TX)* 127(PD6/AIN5/SSI2XDAT3/T4CCP0/U2RTS/USB0EPEN)* 128(PD7/AIN4/NMI/SSI2XDAT2/T4CCP1/U2CTS/USB0PFLT)*; U6 3(NC)*

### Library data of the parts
C21 C22 C25 = CMP-0078241-1: as C7 on sheet TIDA-010281_XDS110_interface_1A
C23 C24 = CMP-0860185-1: CAP, CERM, 8 pF, 50 V,+/- 6.25%, C0G/NP0, 0402; Manufacturer: Yageo; Cap_Case: 0402; Polarized: N; TaMax_C: 125°C; SizeY_mm: 0.5; SizeX_mm: 1; Value: 8pF; AEC Category: Q200; U/M: EA; SizeAreaWB_mm2: 3; TaMin_C: -55°C; SizeZ_mm: 0.6
C26 = CMP-0006352-2: as C9 on sheet TIDA-010281_XDS110_interface_1A
R30 R38 R51 R63 = CMP-0026992-3: as R91 on sheet TIDA-010281_PMIC_BUCK
R39 = CMP-0026993-2: RES, 100, 5%, 0.1 W, AEC-Q200 Grade 0, 0402; Manufacturer: Panasonic; Power_W: 100mW; TempCo: 200 ppm/C; Value_Code: 100R; U/M: EA; Value: 100; EIA_Code: E24; SizeX_mm: 1; SizeY_mm: 0.5; SizeZ_mm: 0.6; Value2: 0.1W; AEC Qualified: Y; AEC Grade: 0; AEC Category: Q200
R57 = CMP-0026992-3: as R92 on sheet TIDA-010281_PMIC_BUCK
R66 R67 R69 R70 = CMP-0027275-3: RES, 33.2, 1%, 0.05 W, 0201; Manufacturer: Vishay-Dale; Power_W: 50mW; TempCo: 200 ppm/C; Value_Code: 33R2; Value: 33.2; EIA_Code: E96; SizeX_mm: 0.6; SizeY_mm: 0.3; SizeZ_mm: 0.26; Value2: 0.05W; SizeArea_mm2: 0.18; AEC Qualified: N; AEC Category: Q200
R68 = CMP-0026404-2: RES, 49.9, 1%, 0.063 W, AEC-Q200 Grade 0, 0402; Manufacturer: Vishay-Dale; Power_W: 63mW; TempCo: 100 ppm/C; Value_Code: 49R9; Value: 49.9; EIA_Code: E96; SizeX_mm: 1; SizeY_mm: 0.5; SizeZ_mm: 0.6; Value2: 0.063W; AEC Qualified: Y; VDC_V: 50V; AEC Category: Q200; AEC Grade: 0
R71 = CMP-0027008-4: RES, 0, 5%, 0.05 W, 0201; Manufacturer: Vishay-Dale; Power_W: 50mW; TempCo: ppm/C; Value_Code: 0000; Value: 0; EIA_Code: E24; SizeX_mm: 0.6; SizeY_mm: 0.3; SizeZ_mm: 0.26; Value2: 0.05W; SizeArea_mm2: 0.18; AEC Qualified: N; AEC Category: Q200
R72-R74 R76 R89 = CMP-0026071-3: as R95 on sheet TIDA-010281_PMIC_BUCK
R87 = CMP-0025958-3: as R123 on sheet TIDA-010281_PMIC_BUCK
R90 = CMP-0026413-2: RES, 4.87 k, 1%, 0.063 W, AEC-Q200 Grade 0, 0402; Manufacturer: Vishay-Dale; Power_W: 63mW; TempCo: 100 ppm/C; Value_Code: 4k87; Value: 4.87k; EIA_Code: E96; SizeX_mm: 1; SizeY_mm: 0.5; SizeZ_mm: 0.6; Value2: 0.063W; AEC Qualified: Y; VDC_V: 50V; AEC Category: Q200; AEC Grade: 0
TP5 = CMP-0078143-3: TEST POINT.  No entry in BOM.
U5 = CMP-0029856-2: Tiva C Series Microcontroller, 1024 KB Flash, 256 KB SRAM, 12 Bit, 20 Channels, -40 to 105 degC, 128-Pin TQFP (PDT), Green (RoHS & no Sb/Br), Tray; Manufacturer: Texas Instruments; ADC Channels: 20; CPU: ARM Cortex-M4; Flash: 1024 KB; ADC Resolution: 12 Bits; Max Speed: 120 MHz; SRAM: 256 KB; SizeAreaWB_mm2: 324.0; SizeArea_mm2: 256.0; SizeX_mm: 16.0; SizeZ_mm: 1.2; CompType: IC
U6 = CMP-0033001-1: Precision Micropower Shunt Voltage Reference, 0.5% accuracy, 2.5 V, 15 ppm / degC, 15 mA, -40 to 125 degC, 3-pin SOT-23 (DBZ), Green (RoHS & no Sb/Br); Manufacturer: Texas Instruments; Initial Accuracy @ 25/deg C(%): 0.5; Temp Coeff(Typ)(ppm/ degree C): 15; Temp Coeff(Max)(ppm/ degree C): 100; Rating: Catalog; Min Iz for Regulation(uA): 75; VO(V): 2.5
Y2 = CMP-0095014-1: 16 MHz ±15ppm Crystal 8pF 80 Ohms 4-SMD, No Lead; Manufacturer: ECS; Frequency Stability: 50ppm; SizeZ_mm: 0.8mm; Frequency_Fixed: 16MHz; AEC Qualified: Yes; Esr: 80; AEC Grade: Grade 1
